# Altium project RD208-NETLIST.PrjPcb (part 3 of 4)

## Sheet 6.SchDoc
size 609 x 444 mm
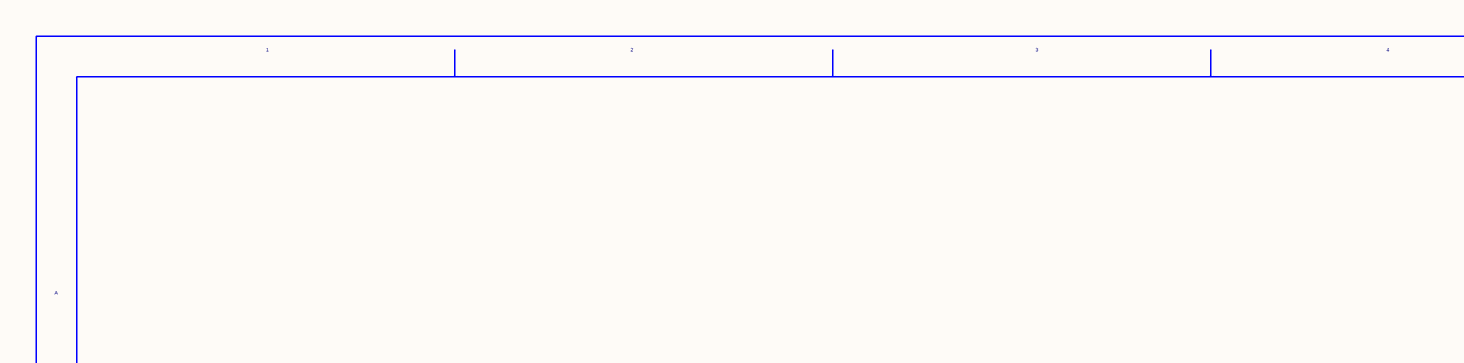
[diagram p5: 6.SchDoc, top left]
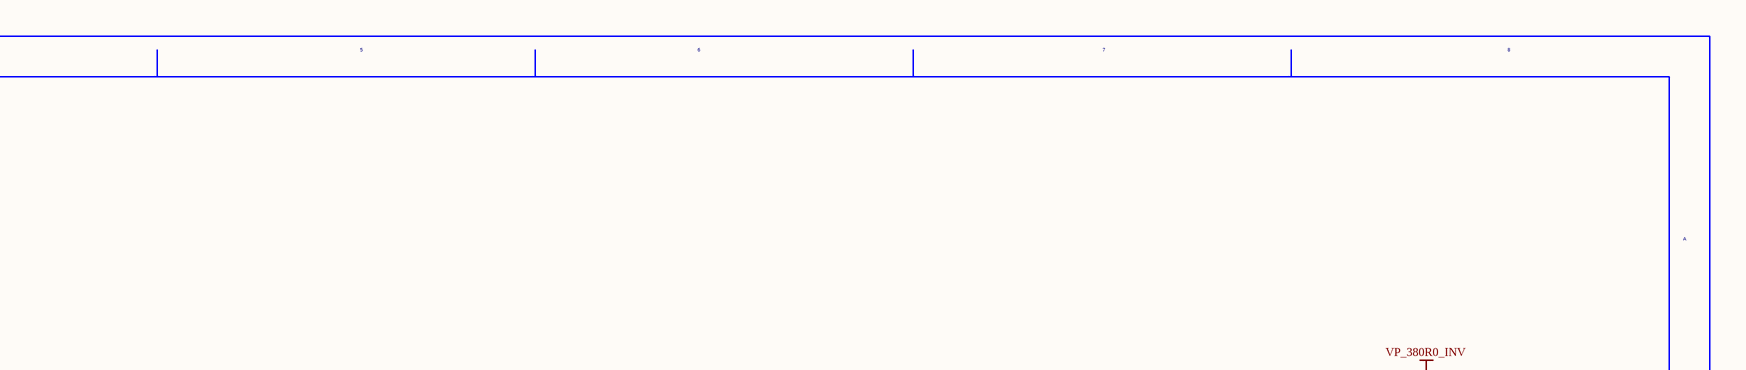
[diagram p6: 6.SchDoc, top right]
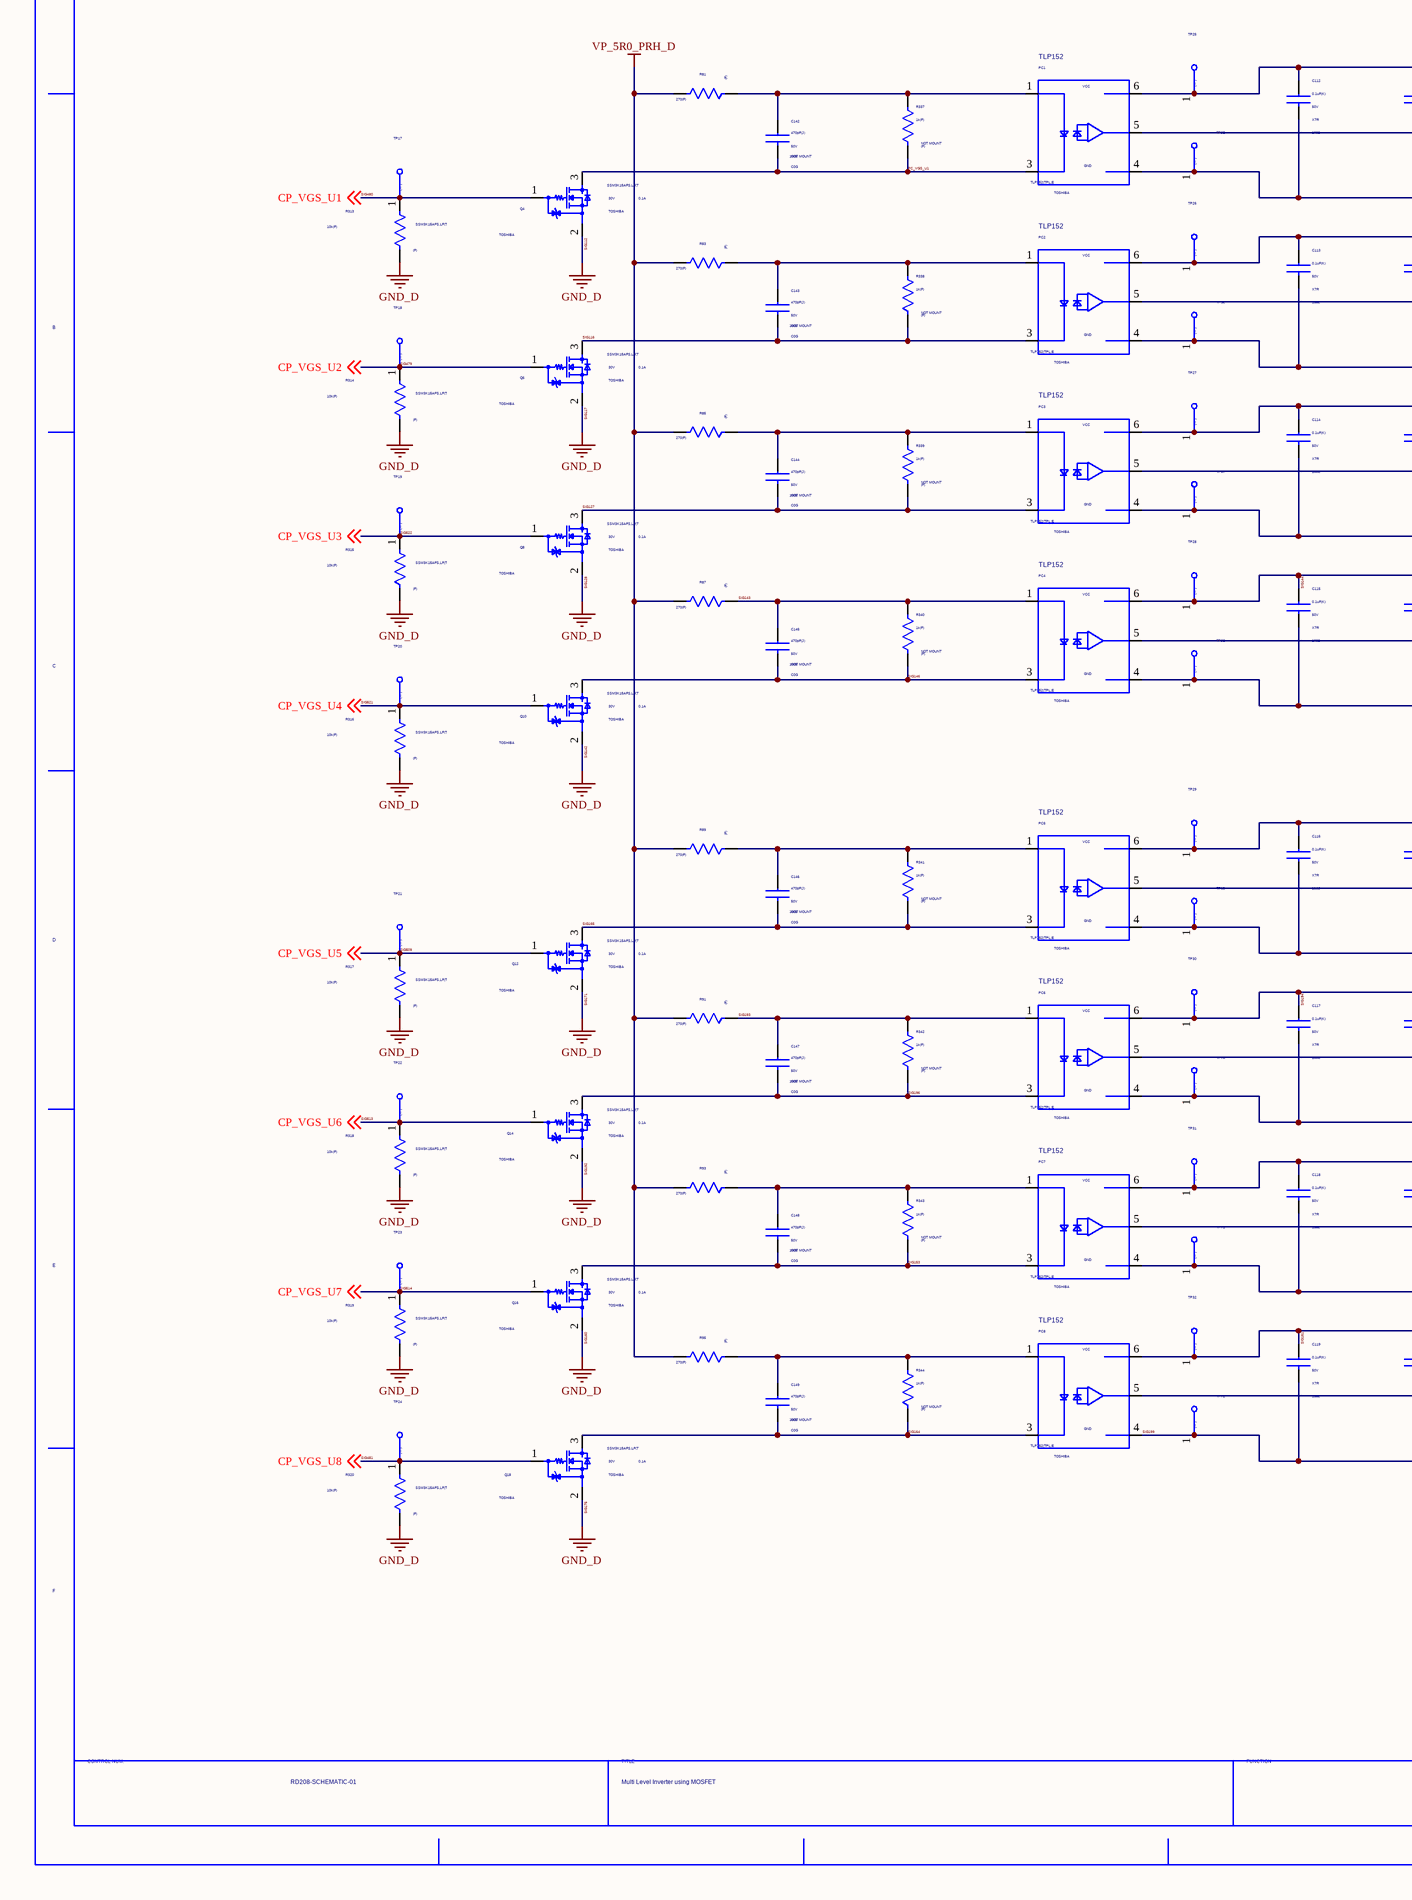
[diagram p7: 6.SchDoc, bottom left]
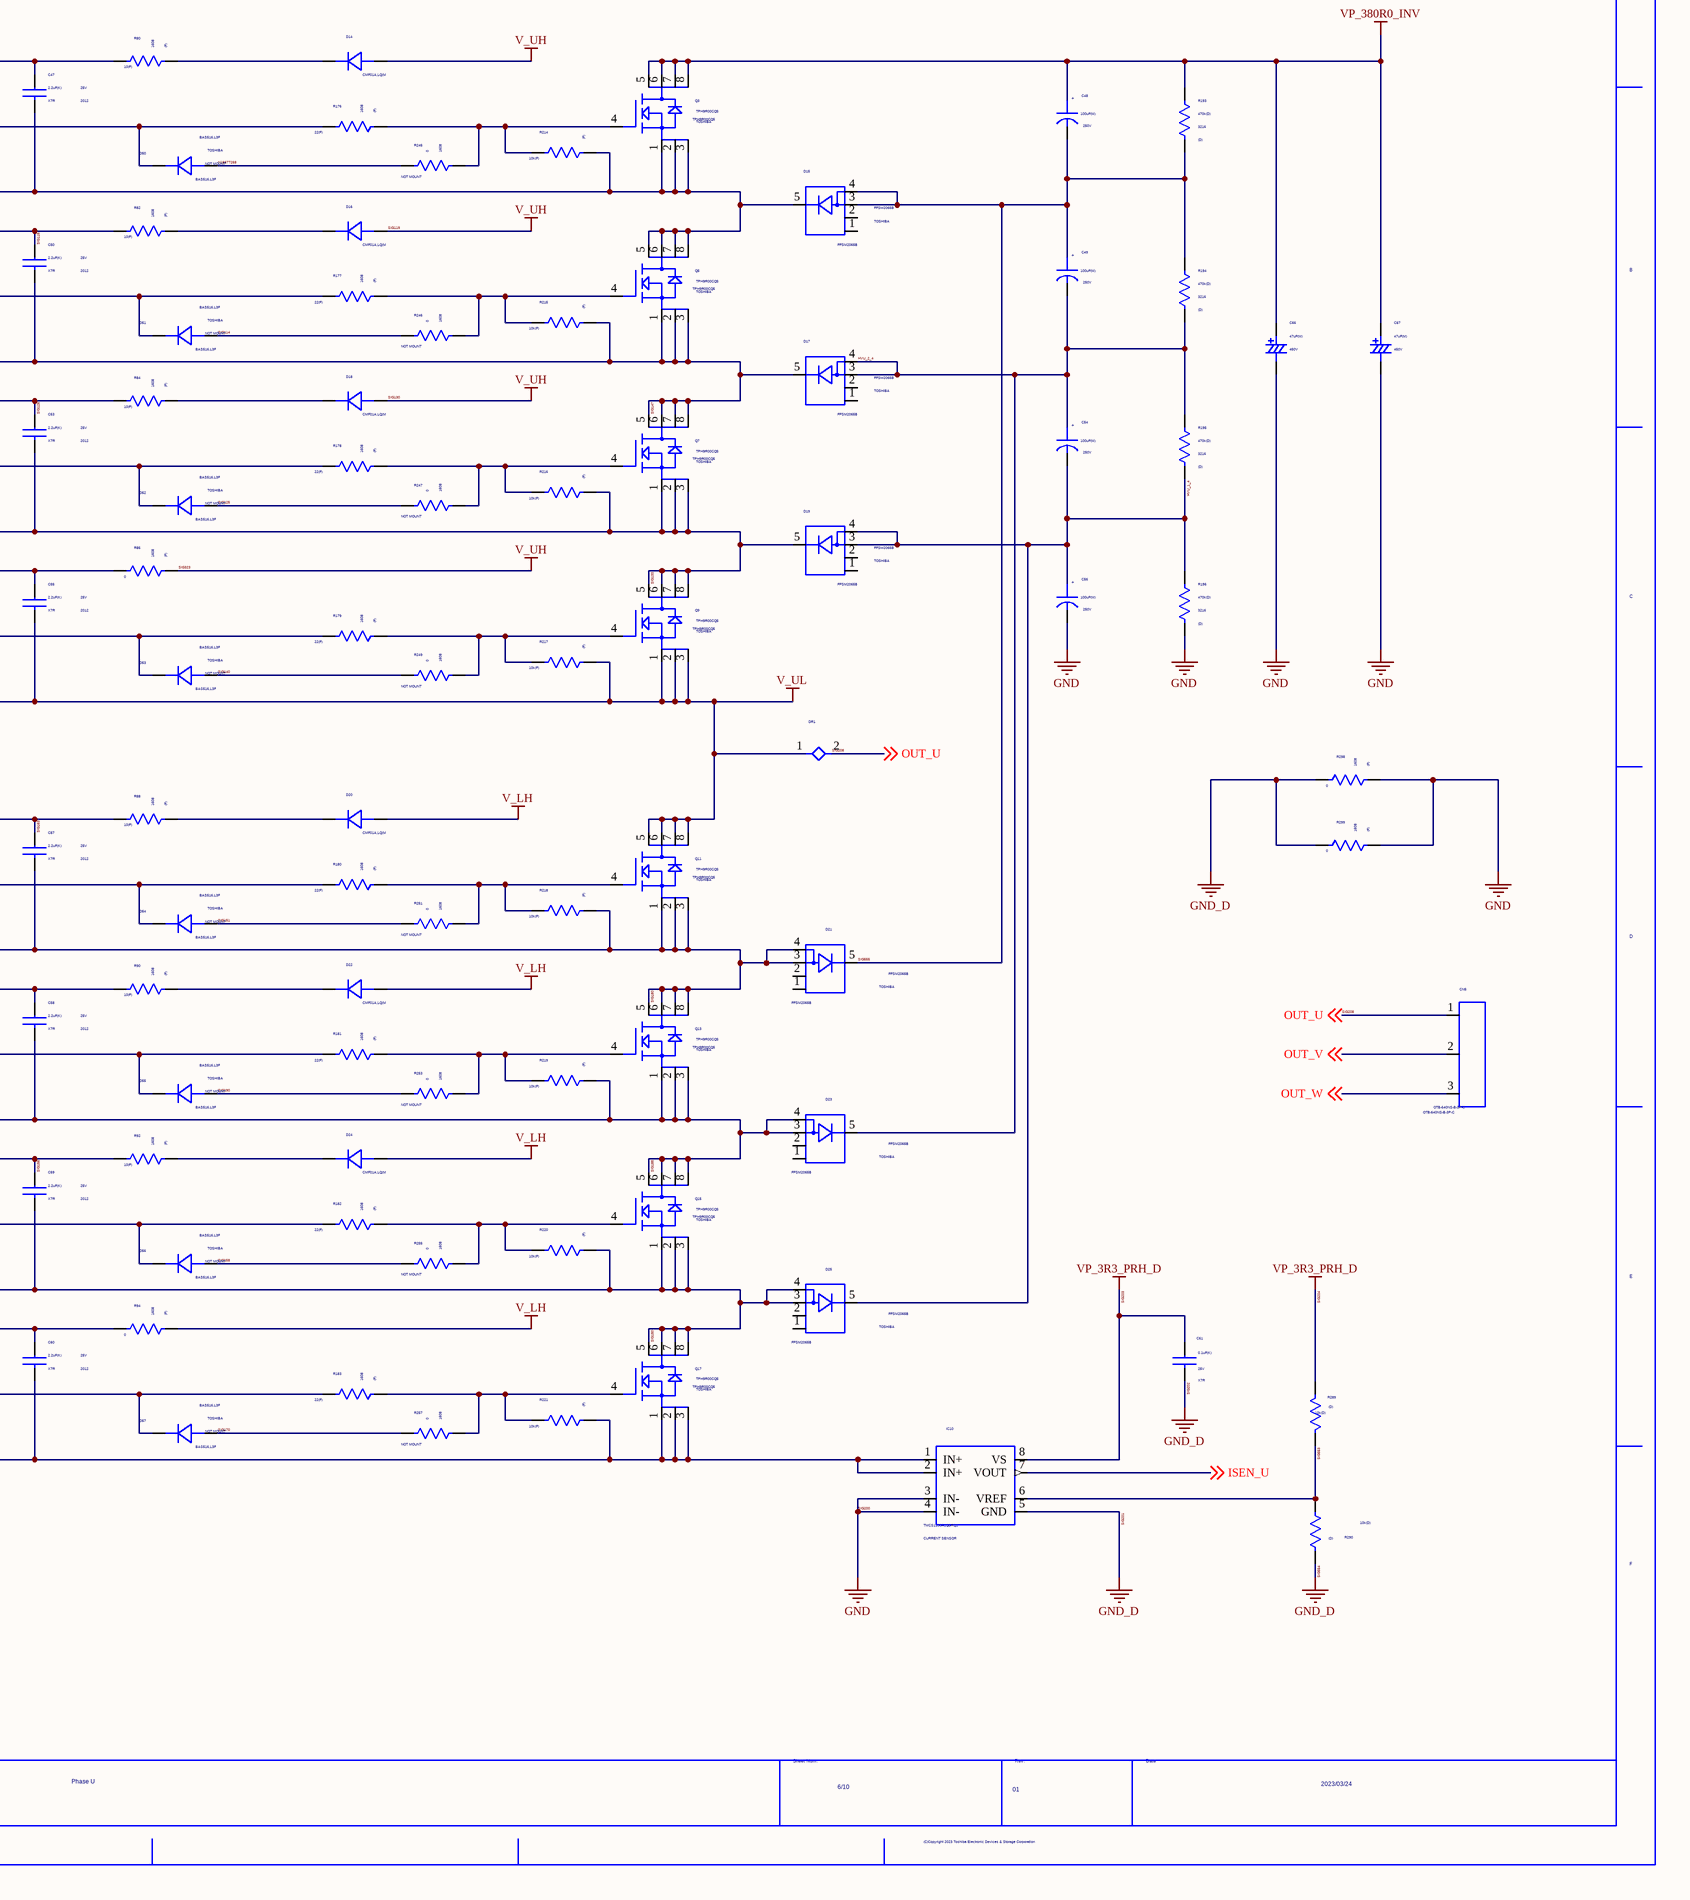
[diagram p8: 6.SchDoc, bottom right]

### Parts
(Parts that share a designator on the sheet are numbered #1, #2 ... from top to bottom, then left to right.)
C47  VAL2: 25V  SIZECODESMD: 2012  VALUE4: X7R  VAL1: 2.2uF(K)  (hidden comment: GRM21BR71E225KE11L)
C48  VAL2: 250V  VAL1: 100uF(M)  (hidden comment: EKMQ251ELL101ML25S)
C49  VAL2: 250V  VAL1: 100uF(M)  (hidden comment: EKMQ251ELL101ML25S)
C50  VAL2: 25V  SIZECODESMD: 2012  VALUE4: X7R  VAL1: 2.2uF(K)  (hidden comment: GRM21BR71E225KE11L)
C53  VAL2: 25V  SIZECODESMD: 2012  VALUE4: X7R  VAL1: 2.2uF(K)  (hidden comment: GRM21BR71E225KE11L)
C54  VAL2: 250V  VAL1: 100uF(M)  (hidden comment: EKMQ251ELL101ML25S)
C55  VAL2: 25V  SIZECODESMD: 2012  VALUE4: X7R  VAL1: 2.2uF(K)  (hidden comment: GRM21BR71E225KE11L)
C56  VAL2: 250V  VAL1: 100uF(M)  (hidden comment: EKMQ251ELL101ML25S)
C57  VAL2: 25V  SIZECODESMD: 2012  VALUE4: X7R  VAL1: 2.2uF(K)  (hidden comment: GRM21BR71E225KE11L)
C58  VAL2: 25V  SIZECODESMD: 2012  VALUE4: X7R  VAL1: 2.2uF(K)  (hidden comment: GRM21BR71E225KE11L)
C59  VAL2: 25V  SIZECODESMD: 2012  VALUE4: X7R  VAL1: 2.2uF(K)  (hidden comment: GRM21BR71E225KE11L)
C60  VAL2: 25V  SIZECODESMD: 2012  VALUE4: X7R  VAL1: 2.2uF(K)  (hidden comment: GRM21BR71E225KE11L)
C61  VAL2: 25V  VALUE4: X7R  VAL1: 0.1uF(K)  (hidden comment: GRM155R71E104KE14D)
C66  VAL2: 450V  VAL1: 47uF(M)  (hidden comment: EKXF451ELL470MM25S)
C67  VAL2: 450V  VAL1: 47uF(M)  (hidden comment: EKXF451ELL470MM25S)
C112  VAL2: 50V  SIZECODESMD: 1608  VALUE4: X7R  VAL1: 0.1uF(K)  (hidden comment: C1608X7R1H104K080AA)
C113  VAL2: 50V  SIZECODESMD: 1608  VALUE4: X7R  VAL1: 0.1uF(K)  (hidden comment: C1608X7R1H104K080AA)
C114  VAL2: 50V  SIZECODESMD: 1608  VALUE4: X7R  VAL1: 0.1uF(K)  (hidden comment: C1608X7R1H104K080AA)
C115  VAL2: 50V  SIZECODESMD: 1608  VALUE4: X7R  VAL1: 0.1uF(K)  (hidden comment: C1608X7R1H104K080AA)
C116  VAL2: 50V  SIZECODESMD: 1608  VALUE4: X7R  VAL1: 0.1uF(K)  (hidden comment: C1608X7R1H104K080AA)
C117  VAL2: 50V  SIZECODESMD: 1608  VALUE4: X7R  VAL1: 0.1uF(K)  (hidden comment: C1608X7R1H104K080AA)
C118  VAL2: 50V  SIZECODESMD: 1608  VALUE4: X7R  VAL1: 0.1uF(K)  (hidden comment: C1608X7R1H104K080AA)
C119  VAL2: 50V  SIZECODESMD: 1608  VALUE4: X7R  VAL1: 0.1uF(K)  (hidden comment: C1608X7R1H104K080AA)
C142  VAL2: 50V  SIZECODESMD: 1005  VALUE4: C0G  VAL1: 470pF(J)  NOTMOUNT: NOT MOUNT  (hidden comment: GRM1555C1H471JA01J)
C143  VAL2: 50V  SIZECODESMD: 1005  VALUE4: C0G  VAL1: 470pF(J)  NOTMOUNT: NOT MOUNT  (hidden comment: GRM1555C1H471JA01J)
C144  VAL2: 50V  SIZECODESMD: 1005  VALUE4: C0G  VAL1: 470pF(J)  NOTMOUNT: NOT MOUNT  (hidden comment: GRM1555C1H471JA01J)
C145  VAL2: 50V  SIZECODESMD: 1005  VALUE4: C0G  VAL1: 470pF(J)  NOTMOUNT: NOT MOUNT  (hidden comment: GRM1555C1H471JA01J)
C146  VAL2: 50V  SIZECODESMD: 1005  VALUE4: C0G  VAL1: 470pF(J)  NOTMOUNT: NOT MOUNT  (hidden comment: GRM1555C1H471JA01J)
C147  VAL2: 50V  SIZECODESMD: 1005  VALUE4: C0G  VAL1: 470pF(J)  NOTMOUNT: NOT MOUNT  (hidden comment: GRM1555C1H471JA01J)
C148  VAL2: 50V  SIZECODESMD: 1005  VALUE4: C0G  VAL1: 470pF(J)  NOTMOUNT: NOT MOUNT  (hidden comment: GRM1555C1H471JA01J)
C149  VAL2: 50V  SIZECODESMD: 1005  VALUE4: C0G  VAL1: 470pF(J)  NOTMOUNT: NOT MOUNT  (hidden comment: GRM1555C1H471JA01J)
CN5  VAL1: OTB-640NS-B-3P-C  (hidden comment: OTB_640NS_B_3P_C)
D14  VAL1: CMF01A,LQ(M  (hidden comment: CMF01A,LQ_M)
D15  USERCOMPTEXT3: TOSHIBA  (hidden comment: FFSM2065B)
D16  VAL1: CMF01A,LQ(M  (hidden comment: CMF01A,LQ_M)
D17  USERCOMPTEXT3: TOSHIBA  (hidden comment: FFSM2065B)
D18  VAL1: CMF01A,LQ(M  (hidden comment: CMF01A,LQ_M)
D19  USERCOMPTEXT3: TOSHIBA  (hidden comment: FFSM2065B)
D20  VAL1: CMF01A,LQ(M  (hidden comment: CMF01A,LQ_M)
D21  USERCOMPTEXT3: TOSHIBA  (hidden comment: FFSM2065B)
D22  VAL1: CMF01A,LQ(M  (hidden comment: CMF01A,LQ_M)
D23  USERCOMPTEXT3: TOSHIBA  (hidden comment: FFSM2065B)
D24  VAL1: CMF01A,LQ(M  (hidden comment: CMF01A,LQ_M)
D25  USERCOMPTEXT3: TOSHIBA  (hidden comment: FFSM2065B)
D50  USERCOMPTEXT3: TOSHIBA  NOTMOUNT: NOT MOUNT  (hidden comment: BAS516,L3F)
D51  USERCOMPTEXT3: TOSHIBA  NOTMOUNT: NOT MOUNT  (hidden comment: BAS516,L3F)
D52  USERCOMPTEXT3: TOSHIBA  NOTMOUNT: NOT MOUNT  (hidden comment: BAS516,L3F)
D53  USERCOMPTEXT3: TOSHIBA  NOTMOUNT: NOT MOUNT  (hidden comment: BAS516,L3F)
D54  USERCOMPTEXT3: TOSHIBA  NOTMOUNT: NOT MOUNT  (hidden comment: BAS516,L3F)
D55  USERCOMPTEXT3: TOSHIBA  NOTMOUNT: NOT MOUNT  (hidden comment: BAS516,L3F)
D56  USERCOMPTEXT3: TOSHIBA  NOTMOUNT: NOT MOUNT  (hidden comment: BAS516,L3F)
D57  USERCOMPTEXT3: TOSHIBA  NOTMOUNT: NOT MOUNT  (hidden comment: BAS516,L3F)
DR1  STAR2  (value not drawn)
IC10  VAL2: CURRENT SENSOR  (hidden comment: TMCS1100A1QDRQ1)
PC1  SCH_NAME: TLP152  USERCOMPTEXT3: TOSHIBA  VAL3: TLP152(TPL,E  (hidden comment: TLP152_TPL,E)
PC2  SCH_NAME: TLP152  USERCOMPTEXT3: TOSHIBA  VAL3: TLP152(TPL,E  (hidden comment: TLP152_TPL,E)
PC3  SCH_NAME: TLP152  USERCOMPTEXT3: TOSHIBA  VAL3: TLP152(TPL,E  (hidden comment: TLP152_TPL,E)
PC4  SCH_NAME: TLP152  USERCOMPTEXT3: TOSHIBA  VAL3: TLP152(TPL,E  (hidden comment: TLP152_TPL,E)
PC5  SCH_NAME: TLP152  USERCOMPTEXT3: TOSHIBA  VAL3: TLP152(TPL,E  (hidden comment: TLP152_TPL,E)
PC6  SCH_NAME: TLP152  USERCOMPTEXT3: TOSHIBA  VAL3: TLP152(TPL,E  (hidden comment: TLP152_TPL,E)
PC7  SCH_NAME: TLP152  USERCOMPTEXT3: TOSHIBA  VAL3: TLP152(TPL,E  (hidden comment: TLP152_TPL,E)
PC8  SCH_NAME: TLP152  USERCOMPTEXT3: TOSHIBA  VAL3: TLP152(TPL,E  (hidden comment: TLP152_TPL,E)
Q3  USERCOMPTEXT3: TOSHIBA  (hidden comment: TPH9R00CQ5)
Q4  VAL2: 0.1A  MANUFACTURER: TOSHIBA  SIZECODESMD: 30V  VAL1: SSM3K15AFS,LF(T  (hidden comment: SSM3K15AFS,LF_T)
Q5  USERCOMPTEXT3: TOSHIBA  (hidden comment: TPH9R00CQ5)
Q6  VAL2: 0.1A  MANUFACTURER: TOSHIBA  SIZECODESMD: 30V  VAL1: SSM3K15AFS,LF(T  (hidden comment: SSM3K15AFS,LF_T)
Q7  USERCOMPTEXT3: TOSHIBA  (hidden comment: TPH9R00CQ5)
Q8  VAL2: 0.1A  MANUFACTURER: TOSHIBA  SIZECODESMD: 30V  VAL1: SSM3K15AFS,LF(T  (hidden comment: SSM3K15AFS,LF_T)
Q9  USERCOMPTEXT3: TOSHIBA  (hidden comment: TPH9R00CQ5)
Q10  VAL2: 0.1A  MANUFACTURER: TOSHIBA  SIZECODESMD: 30V  VAL1: SSM3K15AFS,LF(T  (hidden comment: SSM3K15AFS,LF_T)
Q11  USERCOMPTEXT3: TOSHIBA  (hidden comment: TPH9R00CQ5)
Q12  VAL2: 0.1A  MANUFACTURER: TOSHIBA  SIZECODESMD: 30V  VAL1: SSM3K15AFS,LF(T  (hidden comment: SSM3K15AFS,LF_T)
Q13  USERCOMPTEXT3: TOSHIBA  (hidden comment: TPH9R00CQ5)
Q14  VAL2: 0.1A  MANUFACTURER: TOSHIBA  SIZECODESMD: 30V  VAL1: SSM3K15AFS,LF(T  (hidden comment: SSM3K15AFS,LF_T)
Q15  USERCOMPTEXT3: TOSHIBA  (hidden comment: TPH9R00CQ5)
Q16  VAL2: 0.1A  MANUFACTURER: TOSHIBA  SIZECODESMD: 30V  VAL1: SSM3K15AFS,LF(T  (hidden comment: SSM3K15AFS,LF_T)
Q17  USERCOMPTEXT3: TOSHIBA  (hidden comment: TPH9R00CQ5)
Q18  VAL2: 0.1A  MANUFACTURER: TOSHIBA  SIZECODESMD: 30V  VAL1: SSM3K15AFS,LF(T  (hidden comment: SSM3K15AFS,LF_T)
R80  SIZECODESMD: 1608  VALUE4: (F)  VAL1: 10(F)  (hidden comment: ERJ3EKF10R0V)
R81  VALUE4: (F)  VAL1: 270(F)  (hidden comment: ERJ2RKF2700X)
R82  SIZECODESMD: 1608  VALUE4: (F)  VAL1: 10(F)  (hidden comment: ERJ3EKF10R0V)
R83  VALUE4: (F)  VAL1: 270(F)  (hidden comment: ERJ2RKF2700X)
R84  SIZECODESMD: 1608  VALUE4: (F)  VAL1: 10(F)  (hidden comment: ERJ3EKF10R0V)
R85  VALUE4: (F)  VAL1: 270(F)  (hidden comment: ERJ2RKF2700X)
R86  SIZECODESMD: 1608  VALUE4: (F)  VAL1: 0  (hidden comment: ERJ3EKF10R0V)
R87  VALUE4: (F)  VAL1: 270(F)  (hidden comment: ERJ2RKF2700X)
R88  SIZECODESMD: 1608  VALUE4: (F)  VAL1: 10(F)  (hidden comment: ERJ3EKF10R0V)
R89  VALUE4: (F)  VAL1: 270(F)  (hidden comment: ERJ2RKF2700X)
R90  SIZECODESMD: 1608  VALUE4: (F)  VAL1: 10(F)  (hidden comment: ERJ3EKF10R0V)
R91  VALUE4: (F)  VAL1: 270(F)  (hidden comment: ERJ2RKF2700X)
R92  SIZECODESMD: 1608  VALUE4: (F)  VAL1: 10(F)  (hidden comment: ERJ3EKF10R0V)
R93  VALUE4: (F)  VAL1: 270(F)  (hidden comment: ERJ2RKF2700X)
R94  SIZECODESMD: 1608  VALUE4: (F)  VAL1: 0  (hidden comment: ERJ3EKF10R0V)
R95  VALUE4: (F)  VAL1: 270(F)  (hidden comment: ERJ2RKF2700X)
R176  SIZECODESMD: 1608  VALUE4: (F)  VAL1: 22(F)  (hidden comment: ERJ3EKF22R0V)
R177  SIZECODESMD: 1608  VALUE4: (F)  VAL1: 22(F)  (hidden comment: ERJ3EKF22R0V)
R178  SIZECODESMD: 1608  VALUE4: (F)  VAL1: 22(F)  (hidden comment: ERJ3EKF22R0V)
R179  SIZECODESMD: 1608  VALUE4: (F)  VAL1: 22(F)  (hidden comment: ERJ3EKF22R0V)
R180  SIZECODESMD: 1608  VALUE4: (F)  VAL1: 22(F)  (hidden comment: ERJ3EKF22R0V)
R181  SIZECODESMD: 1608  VALUE4: (F)  VAL1: 22(F)  (hidden comment: ERJ3EKF22R0V)
R182  SIZECODESMD: 1608  VALUE4: (F)  VAL1: 22(F)  (hidden comment: ERJ3EKF22R0V)
R183  SIZECODESMD: 1608  VALUE4: (F)  VAL1: 22(F)  (hidden comment: ERJ3EKF22R0V)
R193  SIZECODESMD: 3216  VALUE4: (D)  VAL1: 470k(D)  (hidden comment: HV73V2BTTD4703D)
R194  SIZECODESMD: 3216  VALUE4: (D)  VAL1: 470k(D)  (hidden comment: HV73V2BTTD4703D)
R195  SIZECODESMD: 3216  VALUE4: (D)  VAL1: 470k(D)  (hidden comment: HV73V2BTTD4703D)
R196  SIZECODESMD: 3216  VALUE4: (D)  VAL1: 470k(D)  (hidden comment: HV73V2BTTD4703D)
R214  VALUE4: (F)  VAL1: 10k(F)  (hidden comment: ERJ2RKF1002X)
R215  VALUE4: (F)  VAL1: 10k(F)  (hidden comment: ERJ2RKF1002X)
R216  VALUE4: (F)  VAL1: 10k(F)  (hidden comment: ERJ2RKF1002X)
R217  VALUE4: (F)  VAL1: 10k(F)  (hidden comment: ERJ2RKF1002X)
R218  VALUE4: (F)  VAL1: 10k(F)  (hidden comment: ERJ2RKF1002X)
R219  VALUE4: (F)  VAL1: 10k(F)  (hidden comment: ERJ2RKF1002X)
R220  VALUE4: (F)  VAL1: 10k(F)  (hidden comment: ERJ2RKF1002X)
R221  VALUE4: (F)  VAL1: 10k(F)  (hidden comment: ERJ2RKF1002X)
R245  SIZECODESMD: 1608  VAL1: 0  NOTMOUNT: NOT MOUNT  (hidden comment: ERJ3GEY0R00V)
R246  SIZECODESMD: 1608  VAL1: 0  NOTMOUNT: NOT MOUNT  (hidden comment: ERJ3GEY0R00V)
R247  SIZECODESMD: 1608  VAL1: 0  NOTMOUNT: NOT MOUNT  (hidden comment: ERJ3GEY0R00V)
R249  SIZECODESMD: 1608  VAL1: 0  NOTMOUNT: NOT MOUNT  (hidden comment: ERJ3GEY0R00V)
R251  SIZECODESMD: 1608  VAL1: 0  NOTMOUNT: NOT MOUNT  (hidden comment: ERJ3GEY0R00V)
R253  SIZECODESMD: 1608  VAL1: 0  NOTMOUNT: NOT MOUNT  (hidden comment: ERJ3GEY0R00V)
R255  SIZECODESMD: 1608  VAL1: 0  NOTMOUNT: NOT MOUNT  (hidden comment: ERJ3GEY0R00V)
R257  SIZECODESMD: 1608  VAL1: 0  NOTMOUNT: NOT MOUNT  (hidden comment: ERJ3GEY0R00V)
R289  VALUE4: (D)  VAL1: 10k(D)  (hidden comment: RK73G1ETTP1002D)
R290  VALUE4: (D)  VAL1: 10k(D)  (hidden comment: RK73G1ETTP1002D)
R298  SIZECODESMD: 1608  VALUE4: (F)  VAL1: 0  (hidden comment: ERJ3EKF10R0V)
R299  SIZECODESMD: 1608  VALUE4: (F)  VAL1: 0  (hidden comment: ERJ3EKF10R0V)
R313  VALUE4: (F)  VAL1: 10k(F)  (hidden comment: ERJ2RKF1002X)
R314  VALUE4: (F)  VAL1: 10k(F)  (hidden comment: ERJ2RKF1002X)
R315  VALUE4: (F)  VAL1: 10k(F)  (hidden comment: ERJ2RKF1002X)
R316  VALUE4: (F)  VAL1: 10k(F)  (hidden comment: ERJ2RKF1002X)
R317  VALUE4: (F)  VAL1: 10k(F)  (hidden comment: ERJ2RKF1002X)
R318  VALUE4: (F)  VAL1: 10k(F)  (hidden comment: ERJ2RKF1002X)
R319  VALUE4: (F)  VAL1: 10k(F)  (hidden comment: ERJ2RKF1002X)
R320  VALUE4: (F)  VAL1: 10k(F)  (hidden comment: ERJ2RKF1002X)
R337  VALUE4: (F)  VAL1: 1k(F)  NOTMOUNT: NOT MOUNT  (hidden comment: ERJ2RKF1001X)
R338  VALUE4: (F)  VAL1: 1k(F)  NOTMOUNT: NOT MOUNT  (hidden comment: ERJ2RKF1001X)
R339  VALUE4: (F)  VAL1: 1k(F)  NOTMOUNT: NOT MOUNT  (hidden comment: ERJ2RKF1001X)
R340  VALUE4: (F)  VAL1: 1k(F)  NOTMOUNT: NOT MOUNT  (hidden comment: ERJ2RKF1001X)
R341  VALUE4: (F)  VAL1: 1k(F)  NOTMOUNT: NOT MOUNT  (hidden comment: ERJ2RKF1001X)
R342  VALUE4: (F)  VAL1: 1k(F)  NOTMOUNT: NOT MOUNT  (hidden comment: ERJ2RKF1001X)
R343  VALUE4: (F)  VAL1: 1k(F)  NOTMOUNT: NOT MOUNT  (hidden comment: ERJ2RKF1001X)
R344  VALUE4: (F)  VAL1: 1k(F)  NOTMOUNT: NOT MOUNT  (hidden comment: ERJ2RKF1001X)
TP17  TP  (value not drawn)
TP18  TP  (value not drawn)
TP19  TP  (value not drawn)
TP20  TP  (value not drawn)
TP21  TP  (value not drawn)
TP22  TP  (value not drawn)
TP23  TP  (value not drawn)
TP24  TP  (value not drawn)
TP25  TP  (value not drawn)
TP26  TP  (value not drawn)
TP27  TP  (value not drawn)
TP28  TP  (value not drawn)
TP29  TP  (value not drawn)
TP30  TP  (value not drawn)
TP31  TP  (value not drawn)
TP32  TP  (value not drawn)
TP65  TP  (value not drawn)
TP66  TP  (value not drawn)
TP67  TP  (value not drawn)
TP68  TP  (value not drawn)
TP69  TP  (value not drawn)
TP70  TP  (value not drawn)
TP71  TP  (value not drawn)
TP72  TP  (value not drawn)
U?#6  DATE: 2023/03/24  TITLE: Multi Level Inverter using MOSFET  REVISION: 01  SHEETNUMBER: 6/10  DRAWINGNUMBER: RD208-SCHEMATIC-01  FUNCTION: Phase U  (hidden comment: WAKU_DEF_A3)

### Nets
GND_D: C61.2 IC10.5(GND) Q4.2(E) Q6.2(E) Q8.2(E) Q10.2(E) Q12.2(E) Q14.2(E) Q16.2(E) Q18.2(E) R290.2 R298.1 R299.1 R313.2 R314.2 R315.2 R316.2 R317.2 R318.2 R319.2 R320.2  [also labelled SIG112, SIG117, SIG128, SIG142, SIG160, SIG171, SIG175, SIG192, SIG201, SIG202, SIG554]  [project net SIG10]
SIG119: D14.A(ANODE) D16.A(ANODE) D18.A(ANODE) R86.2  [also labelled SIG130, SIG323, V_UH]
SIG200: C56.2 C66.2 C67.2 IC10.3(IN-) IC10.4(IN-) R196.2 R298.2 R299.2  [also labelled GND]
SIG203: C61.1 IC10.8(VS) R289.2  [also labelled SIG204, VP_3R3_PRH_D]  [project net SIG107]
V_LH: D20.A(ANODE) D22.A(ANODE) D24.A(ANODE) R94.2  [project net SIG235]
V_UL: C55.2 C115.2 DR1.1 PC4.4 Q9.1(S1) Q9.2(S2) Q9.3(S3) Q11.5(D1) Q11.6(D2) Q11.7(D3) Q11.8(D4) R217.2 TP68.1
VP_5R0_PRH_D: R81.1 R83.1 R85.1 R87.1 R89.1 R91.1 R93.1 R95.1  [project net SIG104]
VP_380R0_INV: C48.1 C66.1 C67.1 Q3.5(D1) Q3.6(D2) Q3.7(D3) Q3.8(D4) R193.1  [project net SIG1]
BS_U1: D14.K(CATHODE) R80.2
GD_U1: Q3.4(G) R176.2 R214.1 R245.2
GD_U2: Q5.4(G) R177.2 R215.1 R246.2
GD_U3: Q7.4(G) R178.2 R216.1 R247.2
GD_U5: Q11.4(G) R180.2 R218.1 R251.2
GD_U6: Q13.4(G) R181.2 R219.1 R253.2
GD_U7: Q15.4(G) R182.2 R220.1 R255.2
GD_U8: Q17.4(G) R183.2 R221.1 R257.2
HVU_1_4: C54.2 C56.1 D19.3(ANODE3) D19.4(ANODE4) D25.5(CATHODE) R195.2 R196.1
HVU_2_4: C49.2 C54.1 D17.3(ANODE3) D17.4(ANODE4) D23.5(CATHODE) R194.2 R195.1
ISEN_U: IC10.7(VOUT) ; off-sheet ISEN_U
N16677268: D50.A(ANODE) R245.1
OUT_V: CN5.2 ; off-sheet OUT_V
OUT_W: CN5.3 ; off-sheet OUT_W
PC_ANODE_U1: C142.1 PC1.1 R81.2 R337.1
PC_G_U1: C47.2 C112.2 D15.5(CATHODE) PC1.4 Q3.1(S1) Q3.2(S2) Q3.3(S3) Q5.5(D1) Q5.6(D2) Q5.7(D3) Q5.8(D4) R214.2 TP65.1
PC_GD_U1: D50.K(CATHODE) PC1.5 R176.1
PC_V_U1: C47.1 C112.1 PC1.6 R80.1 TP25.1
PC_VGS_U1: C142.2 PC1.3 Q4.3(C) R337.2
SIG113: C143.1 PC2.1 R83.2 R338.1
SIG114: D51.A(ANODE) R246.1
SIG115: C50.1 C113.1 PC2.6 R82.1 TP26.1
SIG116: C143.2 PC2.3 Q6.3(C) R338.2
SIG122: D51.K(CATHODE) PC2.5 R177.1
SIG123: D16.K(CATHODE) R82.2
SIG124: C144.1 PC3.1 R85.2 R339.1
SIG125: D52.A(ANODE) R247.1
SIG126: C53.1 C114.1 PC3.6 R84.1 TP27.1
SIG127: C144.2 PC3.3 Q8.3(C) R339.2
SIG133: C53.2 C114.2 D19.5(CATHODE) PC3.4 Q7.1(S1) Q7.2(S2) Q7.3(S3) Q9.5(D1) Q9.6(D2) Q9.7(D3) Q9.8(D4) R216.2 TP67.1
SIG134: D52.K(CATHODE) PC3.5 R178.1
SIG136: D53.K(CATHODE) PC4.5 R179.1
SIG137: D18.K(CATHODE) R84.2
SIG140: D53.A(ANODE) R249.1
SIG143: C145.1 PC4.1 R87.2 R340.1
SIG144: C55.1 C115.1 PC4.6 R86.1 TP28.1
SIG145: Q9.4(G) R179.2 R217.1 R249.2
SIG146: C145.2 PC4.3 Q10.3(C) R340.2
SIG147: C50.2 C113.2 D17.5(CATHODE) PC2.4 Q5.1(S1) Q5.2(S2) Q5.3(S3) Q7.5(D1) Q7.6(D2) Q7.7(D3) Q7.8(D4) R215.2 TP66.1
SIG149: C146.1 PC5.1 R89.2 R341.1
SIG150: C59.2 C118.2 D25.3(ANODE3) D25.4(ANODE4) PC7.4 Q15.1(S1) Q15.2(S2) Q15.3(S3) Q17.5(D1) Q17.6(D2) Q17.7(D3) Q17.8(D4) R220.2 TP71.1
SIG151: D54.A(ANODE) R251.1
SIG153: C148.2 PC7.3 Q16.3(C) R343.2
SIG154: C148.1 PC7.1 R93.2 R343.1
SIG156: C59.1 C118.1 PC7.6 R92.1 TP31.1
SIG158: D56.A(ANODE) R255.1
SIG161: C60.1 C119.1 PC8.6 R94.1 TP32.1
SIG163: C57.1 C116.1 PC5.6 R88.1 TP29.1
SIG164: C149.2 PC8.3 Q18.3(C) R344.2
SIG165: C146.2 PC5.3 Q12.3(C) R341.2
SIG166: D57.K(CATHODE) PC8.5 R183.1
SIG170: D57.A(ANODE) R257.1
SIG174: C149.1 PC8.1 R95.2 R344.1
SIG176: D24.K(CATHODE) R92.2
SIG180: C57.2 C116.2 D21.3(ANODE3) D21.4(ANODE4) PC5.4 Q11.1(S1) Q11.2(S2) Q11.3(S3) Q13.5(D1) Q13.6(D2) Q13.7(D3) Q13.8(D4) R218.2 TP69.1
SIG182: D54.K(CATHODE) PC5.5 R180.1
SIG183: D22.K(CATHODE) R90.2
SIG184: D56.K(CATHODE) PC7.5 R182.1
SIG185: C58.2 C117.2 D23.3(ANODE3) D23.4(ANODE4) PC6.4 Q13.1(S1) Q13.2(S2) Q13.3(S3) Q15.5(D1) Q15.6(D2) Q15.7(D3) Q15.8(D4) R219.2 TP70.1
SIG186: D55.K(CATHODE) PC6.5 R181.1
SIG187: D20.K(CATHODE) R88.2
SIG190: D55.A(ANODE) R253.1
SIG193: C147.1 PC6.1 R91.2 R342.1
SIG194: C58.1 C117.1 PC6.6 R90.1 TP30.1
SIG196: C147.2 PC6.3 Q14.3(C) R342.2
SIG199: C60.2 C119.2 IC10.1(IN+) IC10.2(IN+) PC8.4 Q17.1(S1) Q17.2(S2) Q17.3(S3) R221.2 TP72.1
SIG208: CN5.1 DR1.2 ; off-sheet OUT_U  [also labelled OUT_U]
SIG479: Q6.1(B) R314.1 TP18.1 ; off-sheet CP_VGS_U2  [also labelled CP_VGS_U2]
SIG480: Q4.1(B) R313.1 TP17.1 ; off-sheet CP_VGS_U1  [also labelled CP_VGS_U1]
SIG481: Q18.1(B) R320.1 TP24.1 ; off-sheet CP_VGS_U8  [also labelled CP_VGS_U8]
SIG509: Q12.1(B) R317.1 TP21.1 ; off-sheet CP_VGS_U5  [also labelled CP_VGS_U5]
SIG513: Q14.1(B) R318.1 TP22.1 ; off-sheet CP_VGS_U6  [also labelled CP_VGS_U6]
SIG514: Q16.1(B) R319.1 TP23.1 ; off-sheet CP_VGS_U7  [also labelled CP_VGS_U7]
SIG521: Q10.1(B) R316.1 TP20.1 ; off-sheet CP_VGS_U4  [also labelled CP_VGS_U4]
SIG522: Q8.1(B) R315.1 TP19.1 ; off-sheet CP_VGS_U3  [also labelled CP_VGS_U3]
SIG553: IC10.6(VREF) R289.1 R290.1
SIG555: C48.2 C49.1 D15.3(ANODE3) D15.4(ANODE4) D21.5(CATHODE) R193.2 R194.1

Not connected (* = marked no-connect by the designer): D15 1(NC1) 2(NC2); D17 1(NC1) 2(NC2); D19 1(NC1) 2(NC2); D21 1(NC1) 2(NC2); D23 1(NC1) 2(NC2); D25 1(NC1) 2(NC2)

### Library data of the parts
C47 C50 C53 C55 C57-C60 = GRM21BR71E225KE11L: MANUFACTURER: MURATA; ITEM: CAP Ceramic; TIME: 08:44:45; UPDATEUSER: t5459927; SAVECOUNT: 1; OriginalSymbolOrigin: (0,0); INSTANCENAME: INS15860000
C48 = EKMQ251ELL101ML25S: MANUFACTURER: Nippon Chemi-Con; ITEM: CAP ALUM; TIME: 08:44:45; UPDATEUSER: t5459927; SAVECOUNT: 1; OriginalSymbolOrigin: (0,2540); INSTANCENAME: INS16070082
C49 = EKMQ251ELL101ML25S: MANUFACTURER: Nippon Chemi-Con; ITEM: CAP ALUM; TIME: 08:44:45; UPDATEUSER: t5459927; SAVECOUNT: 1; OriginalSymbolOrigin: (0,2540); INSTANCENAME: INS16070102
C54 = EKMQ251ELL101ML25S: MANUFACTURER: Nippon Chemi-Con; ITEM: CAP ALUM; TIME: 08:44:45; UPDATEUSER: t5459927; SAVECOUNT: 1; OriginalSymbolOrigin: (0,2540); INSTANCENAME: INS16070122
C56 = EKMQ251ELL101ML25S: MANUFACTURER: Nippon Chemi-Con; ITEM: CAP ALUM; TIME: 08:44:45; UPDATEUSER: t5459927; SAVECOUNT: 1; OriginalSymbolOrigin: (0,2540); INSTANCENAME: INS16070142
C61 = GRM155R71E104KE14D: MANUFACTURER: MURATA; ITEM: CAP Ceramic; SIZECODESMD: 1005; TIME: 08:44:45; UPDATEUSER: t5459927; SAVECOUNT: 1; OriginalSymbolOrigin: (0,0); INSTANCENAME: INS16776295
C66 = EKXF451ELL470MM25S: MANUFACTURER: Nippon Chemi-Con; ITEM: CAP ALUM; SIZECODESMD: 18.0mm; TIME: 08:44:46; UPDATEUSER: t5459927; SAVECOUNT: 1; OriginalSymbolOrigin: (0,0); INSTANCENAME: INS16806395
C67 = EKXF451ELL470MM25S: MANUFACTURER: Nippon Chemi-Con; ITEM: CAP ALUM; SIZECODESMD: 18.0mm; TIME: 08:44:46; UPDATEUSER: t5459927; SAVECOUNT: 1; OriginalSymbolOrigin: (0,0); INSTANCENAME: INS16806405
C112-C119 = C1608X7R1H104K080AA: MANUFACTURER: TDK; ITEM: CAP Ceramic; TIME: 08:44:45; UPDATEUSER: t5459927; SAVECOUNT: 1; OriginalSymbolOrigin: (0,0); INSTANCENAME: INS16097035
C142-C149 = GRM1555C1H471JA01J: MANUFACTURER: MURATA; ITEM: CAP Ceramic; TIME: 08:44:46; UPDATEUSER: t5459927; SAVECOUNT: 1; OriginalSymbolOrigin: (0,0); INSTANCENAME: INS17224098
CN5 = OTB_640NS_B_3P_C: MANUFACTURER: OSADA; ITEM: Connector; VAL2: 11mm   x3; TIME: 08:44:46; UPDATEUSER: PS4_common_PC; UPDATETIME: 15:40:04; SAVECOUNT: 2; SAVEAREA0: -13992,-20726,15872,1136; OriginalSymbolOrigin: (0,0)
D14 D16 D18 D20 D22 D24 = CMF01A,LQ_M: MANUFACTURER: TOSHIBA; COMP: CMF01A_LQ_M; ITEM: DIODE; TIME: 08:44:46; UPDATEUSER: t5459927; SAVECOUNT: 1; OriginalSymbolOrigin: (0,0); INSTANCENAME: INS15860772
D15 D17 D19 D21 D23 D25 = FFSM2065B: MANUFACTURER: ON_SEMI; ITEM: DIODE; TIME: 08:44:45; UPDATEUSER: t5459927; SAVECOUNT: 1; SAVEAREA0: -3235,-11101,10576,-990; OriginalSymbolOrigin: (0,0); INSTANCENAME: INS16711377
D50-D57 = BAS516,L3F: COMP: BAS516_L3F; ITEM: DIODE; TIME: 08:44:45; UPDATEUSER: t5459927; SAVECOUNT: 1; OriginalSymbolOrigin: (0,0); INSTANCENAME: INS16674713
DR1 = STAR2: TIME: 12:37:47; UPDATEUSER: d5009410; UPDATETIME: 12:51:51; SAVECOUNT: 17; SAVEAREA0: -6564,-5245,9999,5672; OriginalSymbolOrigin: (-2540,2540); COMP: ONEPOINT
IC10 = TMCS1100A1QDRQ1: MANUFACTURER: TI; ITEM: IC CurrentSensor; TIME: 08:44:45; UPDATEUSER: PS4_common_PC; UPDATETIME: 16:01:14; SAVECOUNT: 3; SAVEAREA0: -10605,-15555,25377,840; OriginalSymbolOrigin: (0,0)
PC1-PC8 = TLP152_TPL,E: ITEM: Photocoupler; COMP: TLP152_TPL_E; TIME: 08:44:45; UPDATEUSER: t5459927; SAVECOUNT: 1; OriginalSymbolOrigin: (0,0); INSTANCENAME: INS15861608
Q3 Q5 Q7 Q9 Q11 Q13 Q15 Q17 = TPH9R00CQ5: ITEM: FET; ORDER: 0; TIME: 08:44:45; UPDATEUSER: t5459927; SAVECOUNT: 1; OriginalSymbolOrigin: (0,0); INSTANCENAME: INS15860992
Q4 Q6 Q8 Q10 Q12 Q14 Q16 Q18 = SSM3K15AFS,LF_T: ITEM: Digital Transistor NPN; COMP: SSM3K15AFS-123; ORDER: 0; TIME: 08:44:45; UPDATEUSER: t5459927; SAVECOUNT: 1; OriginalSymbolOrigin: (0,0); INSTANCENAME: INS15859756
R80 R82 R84 R88 R90 R92 = ERJ3EKF10R0V: MANUFACTURER: Panasonic; ITEM: Register; VAL2: 100mW; TIME: 08:44:45; UPDATEUSER: t5459927; SAVECOUNT: 1; OriginalSymbolOrigin: (0,0); INSTANCENAME: INS16646496
R81 R83 R85 R87 R89 R91 R93 R95 = ERJ2RKF2700X: MANUFACTURER: Panasonic; ITEM: Register; VAL2: 100mW; SIZECODESMD: 1005; TIME: 08:44:45; UPDATEUSER: t5459927; SAVECOUNT: 1; OriginalSymbolOrigin: (0,0); INSTANCENAME: INS16151457
R86 R94 R298 R299 = ERJ3EKF10R0V: MANUFACTURER: Panasonic; ITEM: Register; VAL2: 1/10W; COMP: ERJ3GEY0R00V; TIME: 08:44:45; UPDATEUSER: t5459927; SAVECOUNT: 1; OriginalSymbolOrigin: (0,0); INSTANCENAME: INS16646496
R176-R183 = ERJ3EKF22R0V: MANUFACTURER: Panasonic; ITEM: Register; VAL2: 100mW; TIME: 08:44:45; UPDATEUSER: t5459927; SAVECOUNT: 1; OriginalSymbolOrigin: (0,0); INSTANCENAME: INS17210794
R193 = HV73V2BTTD4703D: MANUFACTURER: KOA; ITEM: Register; VAL2: 0.33W; TIME: 08:44:45; UPDATEUSER: t5459927; SAVECOUNT: 1; OriginalSymbolOrigin: (0,0); INSTANCENAME: INS16806843
R194 = HV73V2BTTD4703D: MANUFACTURER: KOA; ITEM: Register; VAL2: 0.33W; TIME: 08:44:45; UPDATEUSER: t5459927; SAVECOUNT: 1; OriginalSymbolOrigin: (0,0); INSTANCENAME: INS16806859
R195 = HV73V2BTTD4703D: MANUFACTURER: KOA; ITEM: Register; VAL2: 0.33W; TIME: 08:44:45; UPDATEUSER: t5459927; SAVECOUNT: 1; OriginalSymbolOrigin: (0,0); INSTANCENAME: INS16806875
R196 = HV73V2BTTD4703D: MANUFACTURER: KOA; ITEM: Register; VAL2: 0.33W; TIME: 08:44:45; UPDATEUSER: t5459927; SAVECOUNT: 1; OriginalSymbolOrigin: (0,0); INSTANCENAME: INS16806891
R214-R221 = ERJ2RKF1002X: MANUFACTURER: Panasonic; ITEM: Register; VAL2: 100mW; SIZECODESMD: 1005; TIME: 08:44:45; UPDATEUSER: t5459927; SAVECOUNT: 1; OriginalSymbolOrigin: (0,0); INSTANCENAME: INS16648754
R245-R247 R249 R251 R253 R255 R257 = ERJ3GEY0R00V: MANUFACTURER: Panasonic; ITEM: Register; VAL2: 1/10W; TIME: 08:44:45; UPDATEUSER: t5459927; SAVECOUNT: 1; OriginalSymbolOrigin: (0,0); INSTANCENAME: INS16674743
R289 = RK73G1ETTP1002D: MANUFACTURER: KOA; ITEM: Register; VAL2: 100mW; SIZECODESMD: 1005; TIME: 08:44:46; UPDATEUSER: t5459927; SAVECOUNT: 1; OriginalSymbolOrigin: (0,0); INSTANCENAME: INS16808670
R290 = RK73G1ETTP1002D: MANUFACTURER: KOA; ITEM: Register; VAL2: 100mW; SIZECODESMD: 1005; TIME: 08:44:46; UPDATEUSER: t5459927; SAVECOUNT: 1; OriginalSymbolOrigin: (0,0); INSTANCENAME: INS16808683
R313-R320 = ERJ2RKF1002X: MANUFACTURER: Panasonic; ITEM: Register; VAL2: 100mW; SIZECODESMD: 1005; TIME: 08:44:45; UPDATEUSER: t5459927; SAVECOUNT: 1; OriginalSymbolOrigin: (0,0); INSTANCENAME: INS17222356
R337-R344 = ERJ2RKF1001X: MANUFACTURER: Panasonic; ITEM: Register; VAL2: 100mW; SIZECODESMD: 1005; TIME: 08:44:45; UPDATEUSER: t5459927; SAVECOUNT: 1; OriginalSymbolOrigin: (0,0); INSTANCENAME: INS17224061
TP17-TP32 TP65-TP72 = TP: TIME: 16:12:21; UPDATEUSER: fukuda-y; UPDATETIME: 16:18:11; SAVECOUNT: 2; SAVEAREA0: -242,-92,12810,7836; OriginalSymbolOrigin: (0,7620); VAL3: TH Hole dia. 1.0; COMP: TP-TH1.0-L1.6
U?#6 = WAKU_DEF_A3: PLOTTIME: HH:MM; SAVEAREA0: -311037,-554865,914355,115662; TIME: 14:30:25; UPDATEUSER: PS4_common_PC; UPDATETIME: 08:25:02; SAVECOUNT: 18; ZONEOFFSETX: 36; ZONEOFFSETY: -24; OriginalSymbolOrigin: (12700,-12700)

## Sheet 7.SchDoc
size 609 x 444 mm
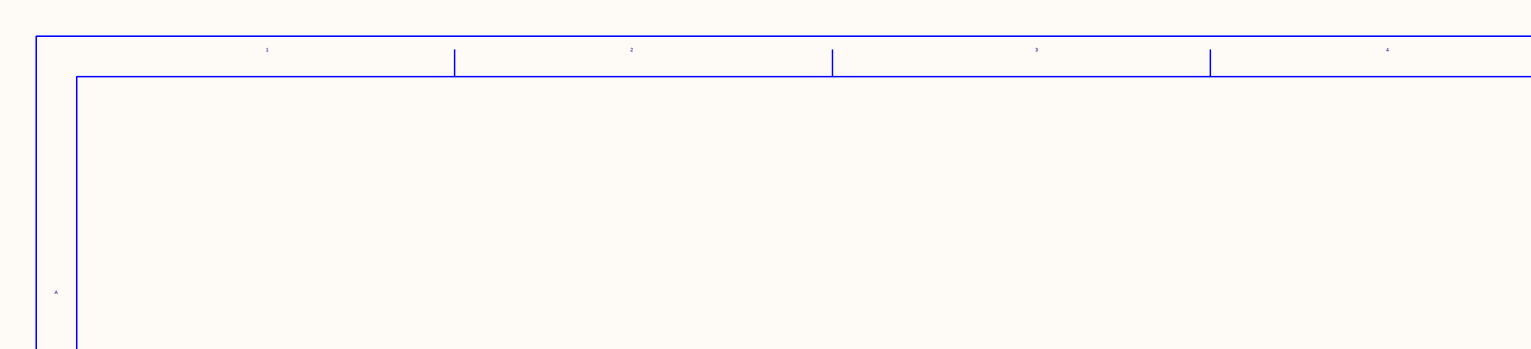
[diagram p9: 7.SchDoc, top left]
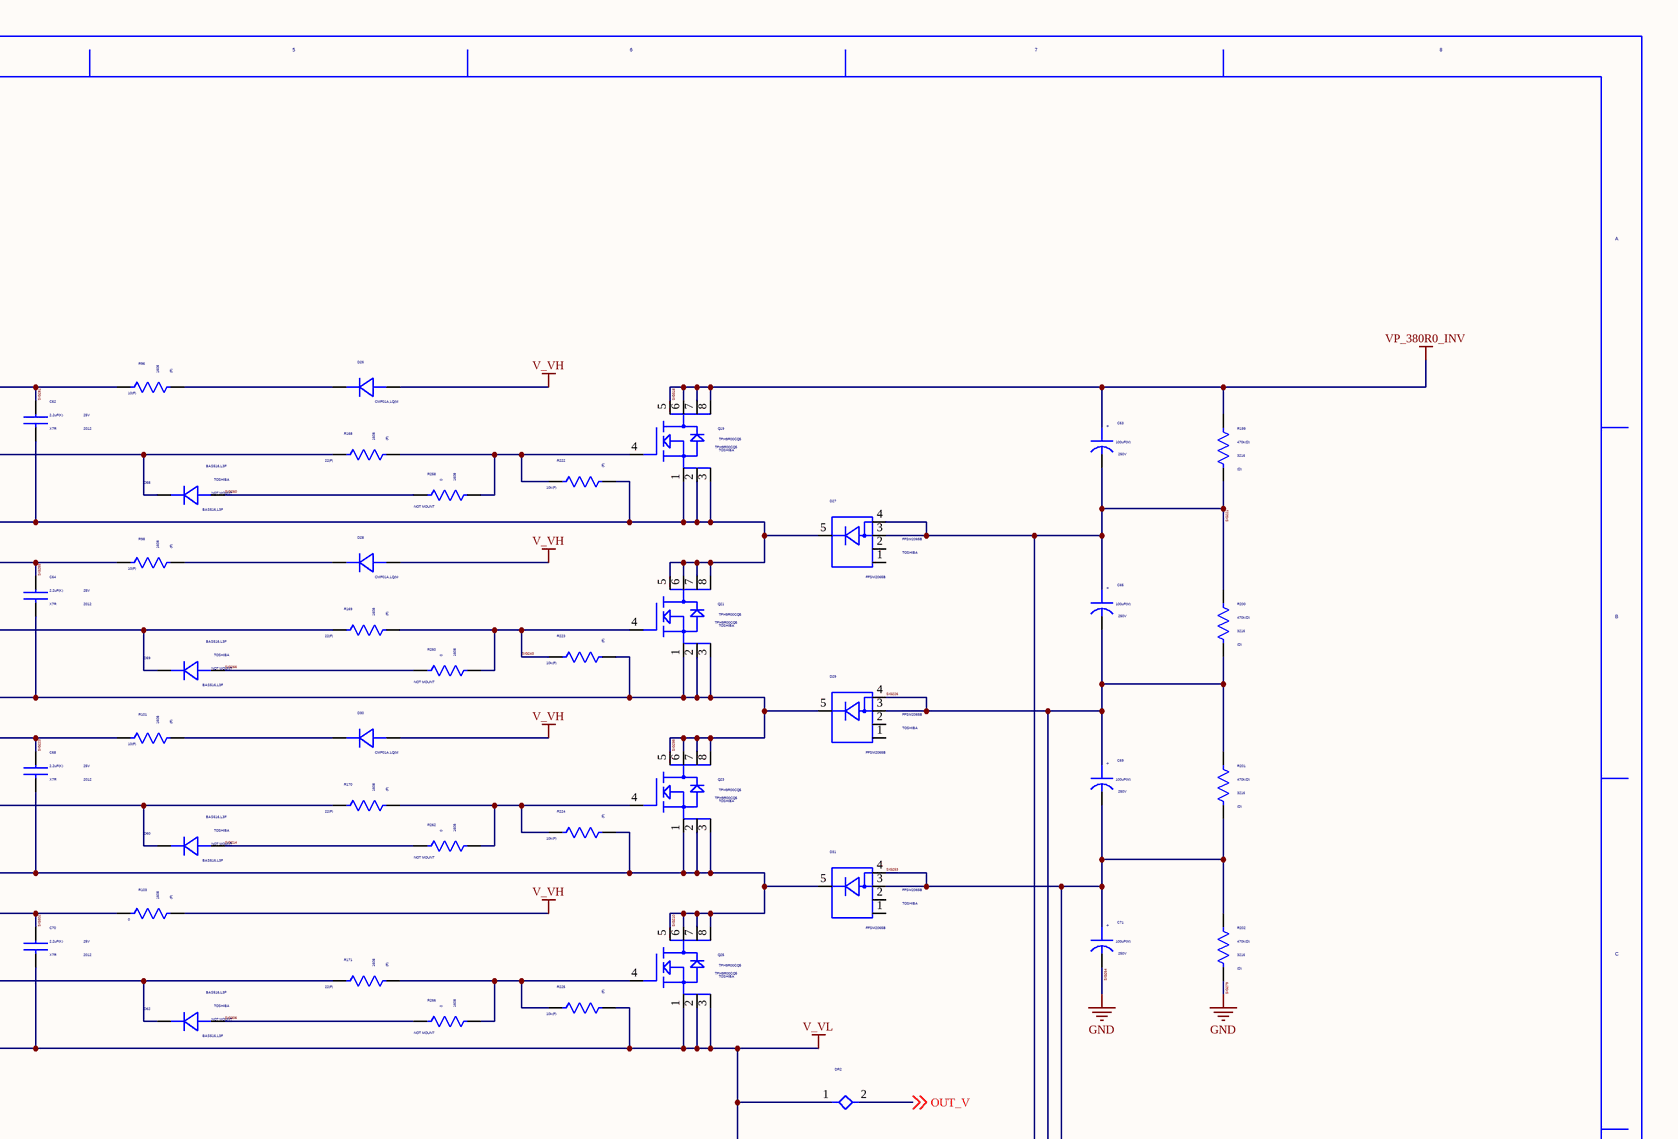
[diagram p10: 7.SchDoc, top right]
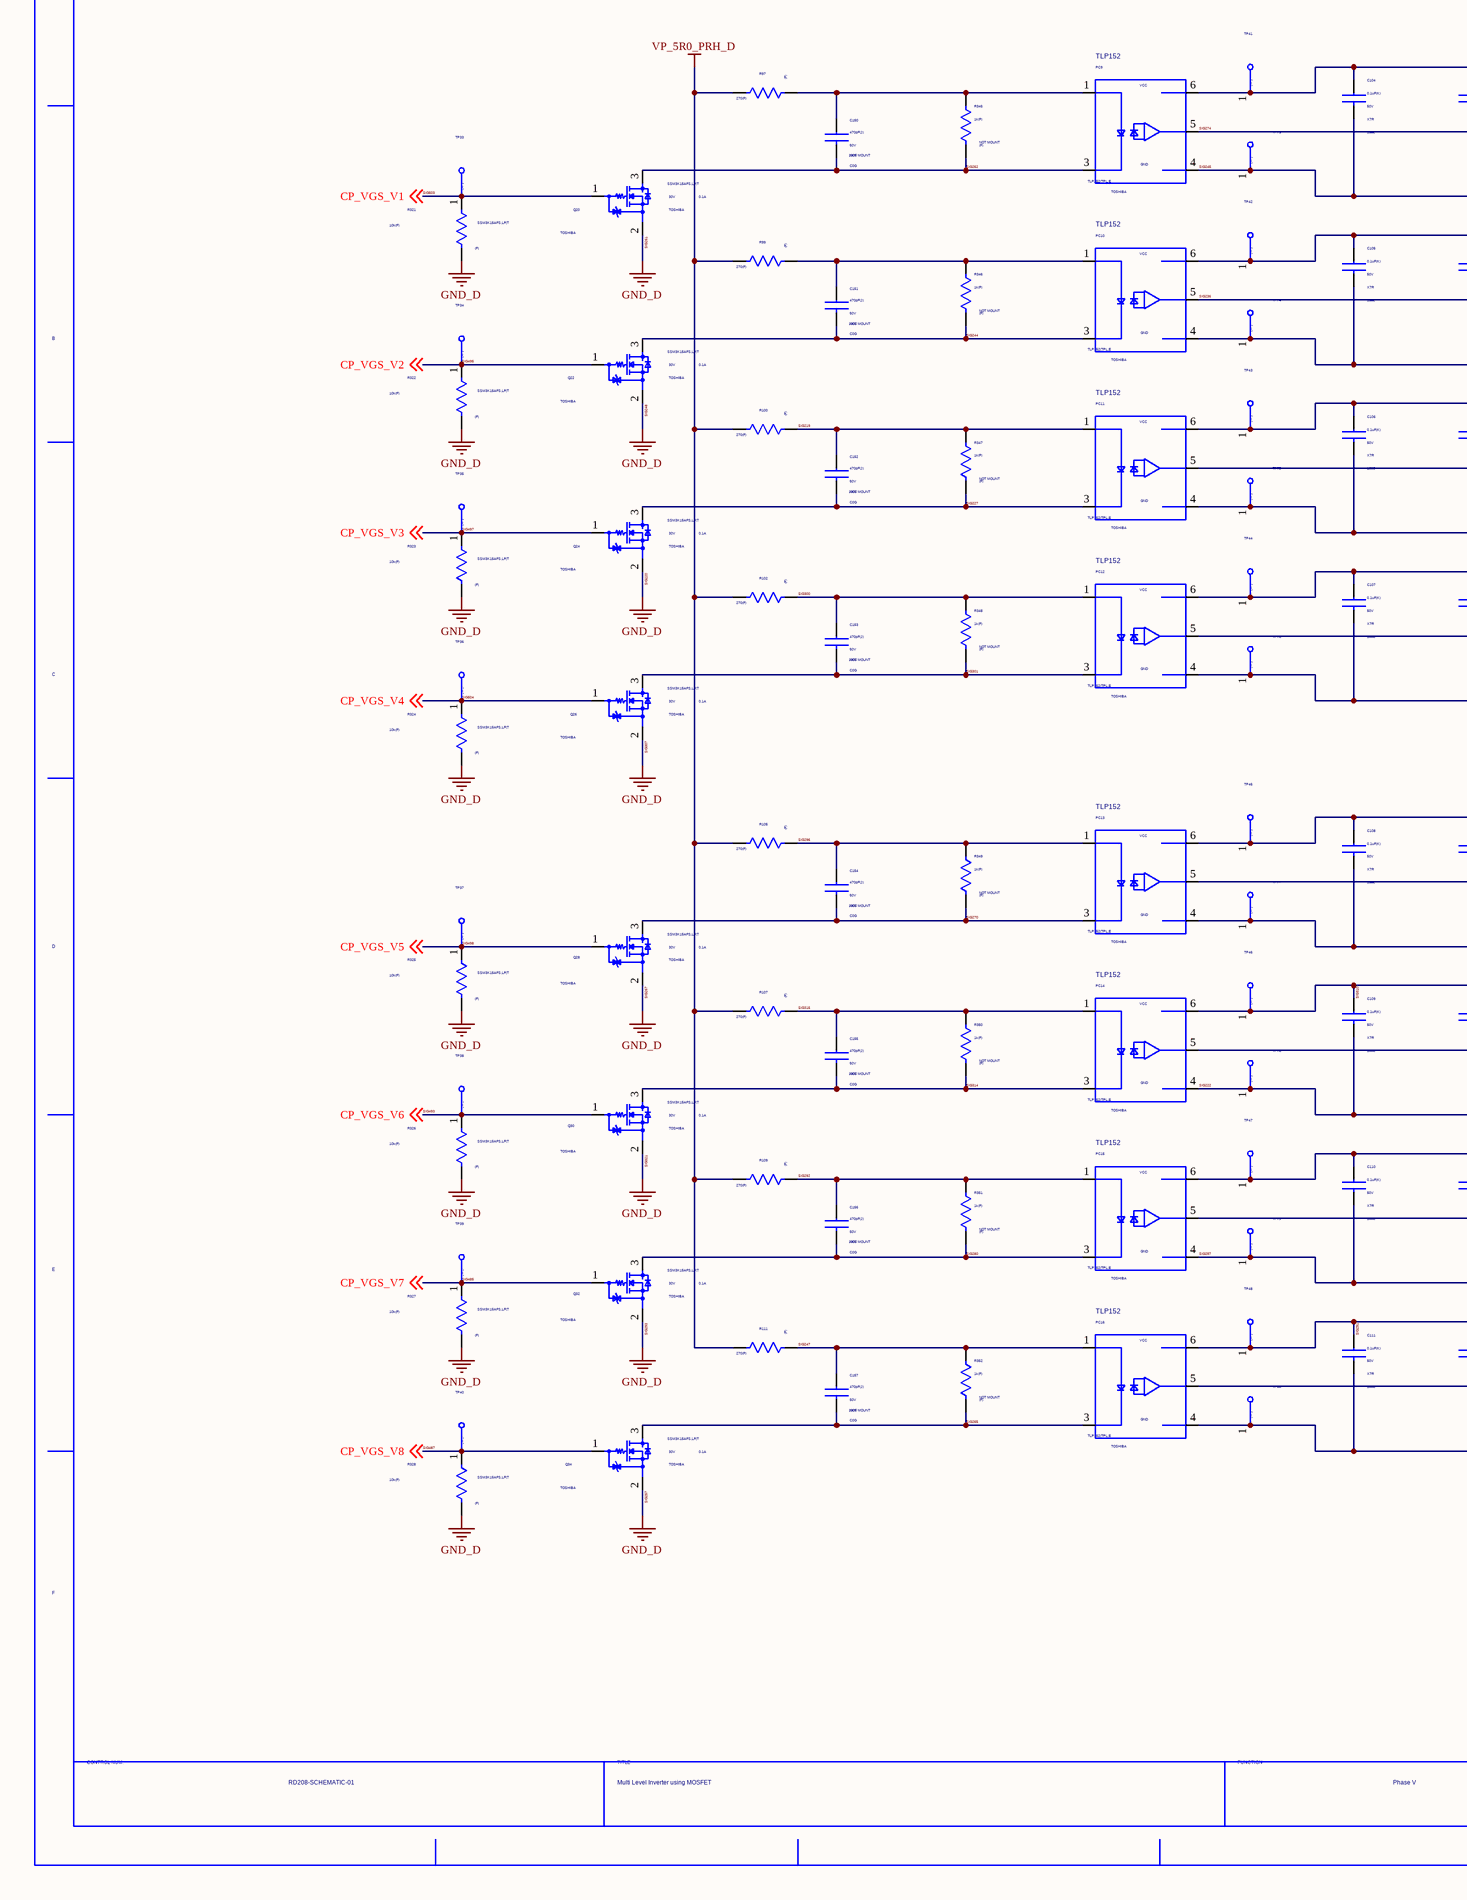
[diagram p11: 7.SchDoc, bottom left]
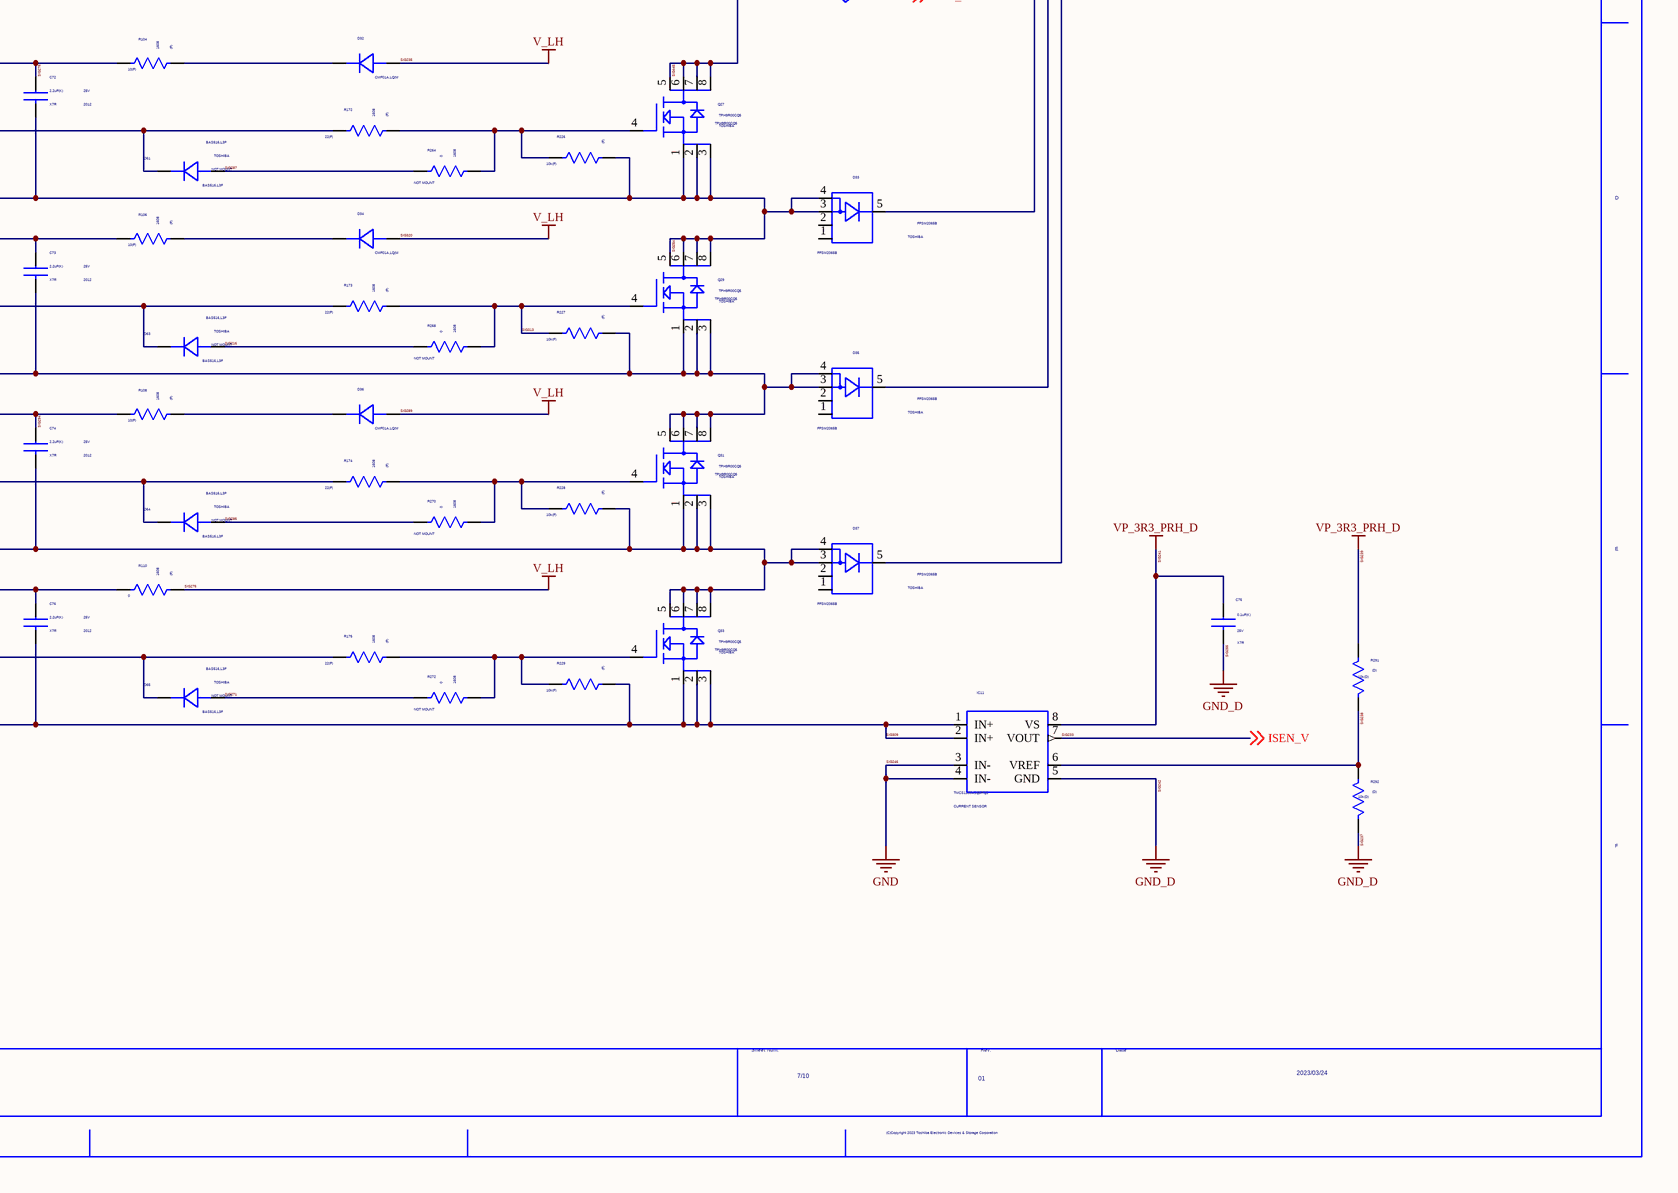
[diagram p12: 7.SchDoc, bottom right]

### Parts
(Parts that share a designator on the sheet are numbered #1, #2 ... from top to bottom, then left to right.)
C62  VAL2: 25V  SIZECODESMD: 2012  VALUE4: X7R  VAL1: 2.2uF(K)  (hidden comment: GRM21BR71E225KE11L)
C63  VAL2: 250V  VAL1: 100uF(M)  (hidden comment: EKMQ251ELL101ML25S)
C64  VAL2: 25V  SIZECODESMD: 2012  VALUE4: X7R  VAL1: 2.2uF(K)  (hidden comment: GRM21BR71E225KE11L)
C65  VAL2: 250V  VAL1: 100uF(M)  (hidden comment: EKMQ251ELL101ML25S)
C68  VAL2: 25V  SIZECODESMD: 2012  VALUE4: X7R  VAL1: 2.2uF(K)  (hidden comment: GRM21BR71E225KE11L)
C69  VAL2: 250V  VAL1: 100uF(M)  (hidden comment: EKMQ251ELL101ML25S)
C70  VAL2: 25V  SIZECODESMD: 2012  VALUE4: X7R  VAL1: 2.2uF(K)  (hidden comment: GRM21BR71E225KE11L)
C71  VAL2: 250V  VAL1: 100uF(M)  (hidden comment: EKMQ251ELL101ML25S)
C72  VAL2: 25V  SIZECODESMD: 2012  VALUE4: X7R  VAL1: 2.2uF(K)  (hidden comment: GRM21BR71E225KE11L)
C73  VAL2: 25V  SIZECODESMD: 2012  VALUE4: X7R  VAL1: 2.2uF(K)  (hidden comment: GRM21BR71E225KE11L)
C74  VAL2: 25V  SIZECODESMD: 2012  VALUE4: X7R  VAL1: 2.2uF(K)  (hidden comment: GRM21BR71E225KE11L)
C75  VAL2: 25V  VALUE4: X7R  VAL1: 0.1uF(K)  (hidden comment: GRM155R71E104KE14D)
C76  VAL2: 25V  SIZECODESMD: 2012  VALUE4: X7R  VAL1: 2.2uF(K)  (hidden comment: GRM21BR71E225KE11L)
C104  VAL2: 50V  SIZECODESMD: 1608  VALUE4: X7R  VAL1: 0.1uF(K)  (hidden comment: C1608X7R1H104K080AA)
C105  VAL2: 50V  SIZECODESMD: 1608  VALUE4: X7R  VAL1: 0.1uF(K)  (hidden comment: C1608X7R1H104K080AA)
C106  VAL2: 50V  SIZECODESMD: 1608  VALUE4: X7R  VAL1: 0.1uF(K)  (hidden comment: C1608X7R1H104K080AA)
C107  VAL2: 50V  SIZECODESMD: 1608  VALUE4: X7R  VAL1: 0.1uF(K)  (hidden comment: C1608X7R1H104K080AA)
C108  VAL2: 50V  SIZECODESMD: 1608  VALUE4: X7R  VAL1: 0.1uF(K)  (hidden comment: C1608X7R1H104K080AA)
C109  VAL2: 50V  SIZECODESMD: 1608  VALUE4: X7R  VAL1: 0.1uF(K)  (hidden comment: C1608X7R1H104K080AA)
C110  VAL2: 50V  SIZECODESMD: 1608  VALUE4: X7R  VAL1: 0.1uF(K)  (hidden comment: C1608X7R1H104K080AA)
C111  VAL2: 50V  SIZECODESMD: 1608  VALUE4: X7R  VAL1: 0.1uF(K)  (hidden comment: C1608X7R1H104K080AA)
C150  VAL2: 50V  SIZECODESMD: 1005  VALUE4: C0G  VAL1: 470pF(J)  NOTMOUNT: NOT MOUNT  (hidden comment: GRM1555C1H471JA01J)
C151  VAL2: 50V  SIZECODESMD: 1005  VALUE4: C0G  VAL1: 470pF(J)  NOTMOUNT: NOT MOUNT  (hidden comment: GRM1555C1H471JA01J)
C152  VAL2: 50V  SIZECODESMD: 1005  VALUE4: C0G  VAL1: 470pF(J)  NOTMOUNT: NOT MOUNT  (hidden comment: GRM1555C1H471JA01J)
C153  VAL2: 50V  SIZECODESMD: 1005  VALUE4: C0G  VAL1: 470pF(J)  NOTMOUNT: NOT MOUNT  (hidden comment: GRM1555C1H471JA01J)
C154  VAL2: 50V  SIZECODESMD: 1005  VALUE4: C0G  VAL1: 470pF(J)  NOTMOUNT: NOT MOUNT  (hidden comment: GRM1555C1H471JA01J)
C155  VAL2: 50V  SIZECODESMD: 1005  VALUE4: C0G  VAL1: 470pF(J)  NOTMOUNT: NOT MOUNT  (hidden comment: GRM1555C1H471JA01J)
C156  VAL2: 50V  SIZECODESMD: 1005  VALUE4: C0G  VAL1: 470pF(J)  NOTMOUNT: NOT MOUNT  (hidden comment: GRM1555C1H471JA01J)
C157  VAL2: 50V  SIZECODESMD: 1005  VALUE4: C0G  VAL1: 470pF(J)  NOTMOUNT: NOT MOUNT  (hidden comment: GRM1555C1H471JA01J)
D26  VAL1: CMF01A,LQ(M  (hidden comment: CMF01A,LQ_M)
D27  USERCOMPTEXT3: TOSHIBA  (hidden comment: FFSM2065B)
D28  VAL1: CMF01A,LQ(M  (hidden comment: CMF01A,LQ_M)
D29  USERCOMPTEXT3: TOSHIBA  (hidden comment: FFSM2065B)
D30  VAL1: CMF01A,LQ(M  (hidden comment: CMF01A,LQ_M)
D31  USERCOMPTEXT3: TOSHIBA  (hidden comment: FFSM2065B)
D32  VAL1: CMF01A,LQ(M  (hidden comment: CMF01A,LQ_M)
D33  USERCOMPTEXT3: TOSHIBA  (hidden comment: FFSM2065B)
D34  VAL1: CMF01A,LQ(M  (hidden comment: CMF01A,LQ_M)
D35  USERCOMPTEXT3: TOSHIBA  (hidden comment: FFSM2065B)
D36  VAL1: CMF01A,LQ(M  (hidden comment: CMF01A,LQ_M)
D37  USERCOMPTEXT3: TOSHIBA  (hidden comment: FFSM2065B)
D58  USERCOMPTEXT3: TOSHIBA  NOTMOUNT: NOT MOUNT  (hidden comment: BAS516,L3F)
D59  USERCOMPTEXT3: TOSHIBA  NOTMOUNT: NOT MOUNT  (hidden comment: BAS516,L3F)
D60  USERCOMPTEXT3: TOSHIBA  NOTMOUNT: NOT MOUNT  (hidden comment: BAS516,L3F)
D61  USERCOMPTEXT3: TOSHIBA  NOTMOUNT: NOT MOUNT  (hidden comment: BAS516,L3F)
D62  USERCOMPTEXT3: TOSHIBA  NOTMOUNT: NOT MOUNT  (hidden comment: BAS516,L3F)
D63  USERCOMPTEXT3: TOSHIBA  NOTMOUNT: NOT MOUNT  (hidden comment: BAS516,L3F)
D64  USERCOMPTEXT3: TOSHIBA  NOTMOUNT: NOT MOUNT  (hidden comment: BAS516,L3F)
D65  USERCOMPTEXT3: TOSHIBA  NOTMOUNT: NOT MOUNT  (hidden comment: BAS516,L3F)
DR2  STAR2  (value not drawn)
IC11  VAL2: CURRENT SENSOR  (hidden comment: TMCS1100A1QDRQ1)
PC9  SCH_NAME: TLP152  USERCOMPTEXT3: TOSHIBA  VAL3: TLP152(TPL,E  (hidden comment: TLP152_TPL,E)
PC10  SCH_NAME: TLP152  USERCOMPTEXT3: TOSHIBA  VAL3: TLP152(TPL,E  (hidden comment: TLP152_TPL,E)
PC11  SCH_NAME: TLP152  USERCOMPTEXT3: TOSHIBA  VAL3: TLP152(TPL,E  (hidden comment: TLP152_TPL,E)
PC12  SCH_NAME: TLP152  USERCOMPTEXT3: TOSHIBA  VAL3: TLP152(TPL,E  (hidden comment: TLP152_TPL,E)
PC13  SCH_NAME: TLP152  USERCOMPTEXT3: TOSHIBA  VAL3: TLP152(TPL,E  (hidden comment: TLP152_TPL,E)
PC14  SCH_NAME: TLP152  USERCOMPTEXT3: TOSHIBA  VAL3: TLP152(TPL,E  (hidden comment: TLP152_TPL,E)
PC15  SCH_NAME: TLP152  USERCOMPTEXT3: TOSHIBA  VAL3: TLP152(TPL,E  (hidden comment: TLP152_TPL,E)
PC16  SCH_NAME: TLP152  USERCOMPTEXT3: TOSHIBA  VAL3: TLP152(TPL,E  (hidden comment: TLP152_TPL,E)
Q19  USERCOMPTEXT3: TOSHIBA  (hidden comment: TPH9R00CQ5)
Q20  VAL2: 0.1A  MANUFACTURER: TOSHIBA  SIZECODESMD: 30V  VAL1: SSM3K15AFS,LF(T  (hidden comment: SSM3K15AFS,LF_T)
Q21  USERCOMPTEXT3: TOSHIBA  (hidden comment: TPH9R00CQ5)
Q22  VAL2: 0.1A  MANUFACTURER: TOSHIBA  SIZECODESMD: 30V  VAL1: SSM3K15AFS,LF(T  (hidden comment: SSM3K15AFS,LF_T)
Q23  USERCOMPTEXT3: TOSHIBA  (hidden comment: TPH9R00CQ5)
Q24  VAL2: 0.1A  MANUFACTURER: TOSHIBA  SIZECODESMD: 30V  VAL1: SSM3K15AFS,LF(T  (hidden comment: SSM3K15AFS,LF_T)
Q25  USERCOMPTEXT3: TOSHIBA  (hidden comment: TPH9R00CQ5)
Q26  VAL2: 0.1A  MANUFACTURER: TOSHIBA  SIZECODESMD: 30V  VAL1: SSM3K15AFS,LF(T  (hidden comment: SSM3K15AFS,LF_T)
Q27  USERCOMPTEXT3: TOSHIBA  (hidden comment: TPH9R00CQ5)
Q28  VAL2: 0.1A  MANUFACTURER: TOSHIBA  SIZECODESMD: 30V  VAL1: SSM3K15AFS,LF(T  (hidden comment: SSM3K15AFS,LF_T)
Q29  USERCOMPTEXT3: TOSHIBA  (hidden comment: TPH9R00CQ5)
Q30  VAL2: 0.1A  MANUFACTURER: TOSHIBA  SIZECODESMD: 30V  VAL1: SSM3K15AFS,LF(T  (hidden comment: SSM3K15AFS,LF_T)
Q31  USERCOMPTEXT3: TOSHIBA  (hidden comment: TPH9R00CQ5)
Q32  VAL2: 0.1A  MANUFACTURER: TOSHIBA  SIZECODESMD: 30V  VAL1: SSM3K15AFS,LF(T  (hidden comment: SSM3K15AFS,LF_T)
Q33  USERCOMPTEXT3: TOSHIBA  (hidden comment: TPH9R00CQ5)
Q34  VAL2: 0.1A  MANUFACTURER: TOSHIBA  SIZECODESMD: 30V  VAL1: SSM3K15AFS,LF(T  (hidden comment: SSM3K15AFS,LF_T)
R96  SIZECODESMD: 1608  VALUE4: (F)  VAL1: 10(F)  (hidden comment: ERJ3EKF10R0V)
R97  VALUE4: (F)  VAL1: 270(F)  (hidden comment: ERJ2RKF2700X)
R98  SIZECODESMD: 1608  VALUE4: (F)  VAL1: 10(F)  (hidden comment: ERJ3EKF10R0V)
R99  VALUE4: (F)  VAL1: 270(F)  (hidden comment: ERJ2RKF2700X)
R100  VALUE4: (F)  VAL1: 270(F)  (hidden comment: ERJ2RKF2700X)
R101  SIZECODESMD: 1608  VALUE4: (F)  VAL1: 10(F)  (hidden comment: ERJ3EKF10R0V)
R102  VALUE4: (F)  VAL1: 270(F)  (hidden comment: ERJ2RKF2700X)
R103  SIZECODESMD: 1608  VALUE4: (F)  VAL1: 0  (hidden comment: ERJ3EKF10R0V)
R104  SIZECODESMD: 1608  VALUE4: (F)  VAL1: 10(F)  (hidden comment: ERJ3EKF10R0V)
R105  VALUE4: (F)  VAL1: 270(F)  (hidden comment: ERJ2RKF2700X)
R106  SIZECODESMD: 1608  VALUE4: (F)  VAL1: 10(F)  (hidden comment: ERJ3EKF10R0V)
R107  VALUE4: (F)  VAL1: 270(F)  (hidden comment: ERJ2RKF2700X)
R108  SIZECODESMD: 1608  VALUE4: (F)  VAL1: 10(F)  (hidden comment: ERJ3EKF10R0V)
R109  VALUE4: (F)  VAL1: 270(F)  (hidden comment: ERJ2RKF2700X)
R110  SIZECODESMD: 1608  VALUE4: (F)  VAL1: 0  (hidden comment: ERJ3EKF10R0V)
R111  VALUE4: (F)  VAL1: 270(F)  (hidden comment: ERJ2RKF2700X)
R168  SIZECODESMD: 1608  VALUE4: (F)  VAL1: 22(F)  (hidden comment: ERJ3EKF22R0V)
R169  SIZECODESMD: 1608  VALUE4: (F)  VAL1: 22(F)  (hidden comment: ERJ3EKF22R0V)
R170  SIZECODESMD: 1608  VALUE4: (F)  VAL1: 22(F)  (hidden comment: ERJ3EKF22R0V)
R171  SIZECODESMD: 1608  VALUE4: (F)  VAL1: 22(F)  (hidden comment: ERJ3EKF22R0V)
R172  SIZECODESMD: 1608  VALUE4: (F)  VAL1: 22(F)  (hidden comment: ERJ3EKF22R0V)
R173  SIZECODESMD: 1608  VALUE4: (F)  VAL1: 22(F)  (hidden comment: ERJ3EKF22R0V)
R174  SIZECODESMD: 1608  VALUE4: (F)  VAL1: 22(F)  (hidden comment: ERJ3EKF22R0V)
R175  SIZECODESMD: 1608  VALUE4: (F)  VAL1: 22(F)  (hidden comment: ERJ3EKF22R0V)
R199  SIZECODESMD: 3216  VALUE4: (D)  VAL1: 470k(D)  (hidden comment: HV73V2BTTD4703D)
R200  SIZECODESMD: 3216  VALUE4: (D)  VAL1: 470k(D)  (hidden comment: HV73V2BTTD4703D)
R201  SIZECODESMD: 3216  VALUE4: (D)  VAL1: 470k(D)  (hidden comment: HV73V2BTTD4703D)
R202  SIZECODESMD: 3216  VALUE4: (D)  VAL1: 470k(D)  (hidden comment: HV73V2BTTD4703D)
R222  VALUE4: (F)  VAL1: 10k(F)  (hidden comment: ERJ2RKF1002X)
R223  VALUE4: (F)  VAL1: 10k(F)  (hidden comment: ERJ2RKF1002X)
R224  VALUE4: (F)  VAL1: 10k(F)  (hidden comment: ERJ2RKF1002X)
R225  VALUE4: (F)  VAL1: 10k(F)  (hidden comment: ERJ2RKF1002X)
R226  VALUE4: (F)  VAL1: 10k(F)  (hidden comment: ERJ2RKF1002X)
R227  VALUE4: (F)  VAL1: 10k(F)  (hidden comment: ERJ2RKF1002X)
R228  VALUE4: (F)  VAL1: 10k(F)  (hidden comment: ERJ2RKF1002X)
R229  VALUE4: (F)  VAL1: 10k(F)  (hidden comment: ERJ2RKF1002X)
R258  SIZECODESMD: 1608  VAL1: 0  NOTMOUNT: NOT MOUNT  (hidden comment: ERJ3GEY0R00V)
R260  SIZECODESMD: 1608  VAL1: 0  NOTMOUNT: NOT MOUNT  (hidden comment: ERJ3GEY0R00V)
R262  SIZECODESMD: 1608  VAL1: 0  NOTMOUNT: NOT MOUNT  (hidden comment: ERJ3GEY0R00V)
R264  SIZECODESMD: 1608  VAL1: 0  NOTMOUNT: NOT MOUNT  (hidden comment: ERJ3GEY0R00V)
R266  SIZECODESMD: 1608  VAL1: 0  NOTMOUNT: NOT MOUNT  (hidden comment: ERJ3GEY0R00V)
R268  SIZECODESMD: 1608  VAL1: 0  NOTMOUNT: NOT MOUNT  (hidden comment: ERJ3GEY0R00V)
R270  SIZECODESMD: 1608  VAL1: 0  NOTMOUNT: NOT MOUNT  (hidden comment: ERJ3GEY0R00V)
R272  SIZECODESMD: 1608  VAL1: 0  NOTMOUNT: NOT MOUNT  (hidden comment: ERJ3GEY0R00V)
R291  VALUE4: (D)  VAL1: 10k(D)  (hidden comment: RK73G1ETTP1002D)
R292  VALUE4: (D)  VAL1: 10k(D)  (hidden comment: RK73G1ETTP1002D)
R321  VALUE4: (F)  VAL1: 10k(F)  (hidden comment: ERJ2RKF1002X)
R322  VALUE4: (F)  VAL1: 10k(F)  (hidden comment: ERJ2RKF1002X)
R323  VALUE4: (F)  VAL1: 10k(F)  (hidden comment: ERJ2RKF1002X)
R324  VALUE4: (F)  VAL1: 10k(F)  (hidden comment: ERJ2RKF1002X)
R325  VALUE4: (F)  VAL1: 10k(F)  (hidden comment: ERJ2RKF1002X)
R326  VALUE4: (F)  VAL1: 10k(F)  (hidden comment: ERJ2RKF1002X)
R327  VALUE4: (F)  VAL1: 10k(F)  (hidden comment: ERJ2RKF1002X)
R328  VALUE4: (F)  VAL1: 10k(F)  (hidden comment: ERJ2RKF1002X)
R345  VALUE4: (F)  VAL1: 1k(F)  NOTMOUNT: NOT MOUNT  (hidden comment: ERJ2RKF1001X)
R346  VALUE4: (F)  VAL1: 1k(F)  NOTMOUNT: NOT MOUNT  (hidden comment: ERJ2RKF1001X)
R347  VALUE4: (F)  VAL1: 1k(F)  NOTMOUNT: NOT MOUNT  (hidden comment: ERJ2RKF1001X)
R348  VALUE4: (F)  VAL1: 1k(F)  NOTMOUNT: NOT MOUNT  (hidden comment: ERJ2RKF1001X)
R349  VALUE4: (F)  VAL1: 1k(F)  NOTMOUNT: NOT MOUNT  (hidden comment: ERJ2RKF1001X)
R350  VALUE4: (F)  VAL1: 1k(F)  NOTMOUNT: NOT MOUNT  (hidden comment: ERJ2RKF1001X)
R351  VALUE4: (F)  VAL1: 1k(F)  NOTMOUNT: NOT MOUNT  (hidden comment: ERJ2RKF1001X)
R352  VALUE4: (F)  VAL1: 1k(F)  NOTMOUNT: NOT MOUNT  (hidden comment: ERJ2RKF1001X)
TP33  TP  (value not drawn)
TP34  TP  (value not drawn)
TP35  TP  (value not drawn)
TP36  TP  (value not drawn)
TP37  TP  (value not drawn)
TP38  TP  (value not drawn)
TP39  TP  (value not drawn)
TP40  TP  (value not drawn)
TP41  TP  (value not drawn)
TP42  TP  (value not drawn)
TP43  TP  (value not drawn)
TP44  TP  (value not drawn)
TP45  TP  (value not drawn)
TP46  TP  (value not drawn)
TP47  TP  (value not drawn)
TP48  TP  (value not drawn)
TP73  TP  (value not drawn)
TP74  TP  (value not drawn)
TP75  TP  (value not drawn)
TP76  TP  (value not drawn)
TP77  TP  (value not drawn)
TP78  TP  (value not drawn)
TP79  TP  (value not drawn)
TP80  TP  (value not drawn)
U?#7  DATE: 2023/03/24  TITLE: Multi Level Inverter using MOSFET  REVISION: 01  SHEETNUMBER: 7/10  DRAWINGNUMBER: RD208-SCHEMATIC-01  FUNCTION: Phase V  (hidden comment: WAKU_DEF_A3)

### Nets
GND: C71.2 IC11.3(IN-) IC11.4(IN-) R202.2  [also labelled SIG246, SIG264, SIG279]  [project net SIG200]
GND_D: C75.2 IC11.5(GND) Q20.2(E) Q22.2(E) Q24.2(E) Q26.2(E) Q28.2(E) Q30.2(E) Q32.2(E) Q34.2(E) R292.1 R321.2 R322.2 R323.2 R324.2 R325.2 R326.2 R327.2 R328.2  [also labelled SIG220, SIG237, SIG242, SIG248, SIG255, SIG257, SIG261, SIG267, SIG293, SIG307, SIG321]  [project net SIG10]
SIG235: D32.A(ANODE) D34.A(ANODE) D36.A(ANODE) R110.2  [also labelled SIG275, SIG289, SIG320, V_LH]
SIG239: C75.1 IC11.8(VS) R291.2  [also labelled SIG241, VP_3R3_PRH_D]  [project net SIG107]
SIG318: C63.1 Q19.5(D1) Q19.6(D2) Q19.7(D3) Q19.8(D4) R199.1  [also labelled VP_380R0_INV]  [project net SIG1]
SIG445: C70.2 C107.2 DR2.1 PC12.4 Q25.1(S1) Q25.2(S2) Q25.3(S3) Q27.5(D1) Q27.6(D2) Q27.7(D3) Q27.8(D4) R225.2 TP76.1  [also labelled V_VL]
V_VH: D26.A(ANODE) D28.A(ANODE) D30.A(ANODE) R103.2
VP_5R0_PRH_D: R97.1 R99.1 R100.1 R102.1 R105.1 R107.1 R109.1 R111.1  [project net SIG104]
OUT_V: DR2.2 ; off-sheet OUT_V
SIG209: D60.K(CATHODE) PC11.5 R170.1
SIG210: C68.2 C106.2 D31.5(CATHODE) PC11.4 Q23.1(S1) Q23.2(S2) Q23.3(S3) Q25.5(D1) Q25.6(D2) Q25.7(D3) Q25.8(D4) R224.2 TP75.1
SIG214: D60.A(ANODE) R262.1
SIG215: D32.K(CATHODE) R104.2
SIG216: D63.A(ANODE) R268.1
SIG219: C152.1 PC11.1 R100.2 R347.1
SIG221: C63.2 C65.1 D27.3(ANODE3) D27.4(ANODE4) D33.5(CATHODE) R199.2 R200.1
SIG222: C73.2 C109.2 D35.3(ANODE3) D35.4(ANODE4) PC14.4 Q29.1(S1) Q29.2(S2) Q29.3(S3) Q31.5(D1) Q31.6(D2) Q31.7(D3) Q31.8(D4) R227.2 TP78.1
SIG223: C68.1 C106.1 PC11.6 R101.1 TP43.1
SIG225: D61.K(CATHODE) PC13.5 R172.1
SIG226: C65.2 C69.1 D29.3(ANODE3) D29.4(ANODE4) D35.5(CATHODE) R200.2 R201.1
SIG227: C152.2 PC11.3 Q24.3(C) R347.2
SIG230: D28.K(CATHODE) R98.2
SIG231: D64.K(CATHODE) PC15.5 R174.1
SIG232: D34.K(CATHODE) R106.2
SIG233: IC11.7(VOUT) ; off-sheet ISEN_V  [also labelled ISEN_V]
SIG236: D59.K(CATHODE) PC10.5 R169.1
SIG238: IC11.6(VREF) R291.1 R292.2
SIG243: Q21.4(G) R169.2 R223.1 R260.2
SIG244: C151.2 PC10.3 Q22.3(C) R346.2
SIG245: C62.2 C104.2 D27.5(CATHODE) PC9.4 Q19.1(S1) Q19.2(S2) Q19.3(S3) Q21.5(D1) Q21.6(D2) Q21.7(D3) Q21.8(D4) R222.2 TP73.1
SIG247: C157.1 PC16.1 R111.2 R352.1
SIG252: D36.K(CATHODE) R108.2
SIG253: C69.2 C71.1 D31.3(ANODE3) D31.4(ANODE4) D37.5(CATHODE) R201.2 R202.1
SIG254: C72.2 C108.2 D33.3(ANODE3) D33.4(ANODE4) PC13.4 Q27.1(S1) Q27.2(S2) Q27.3(S3) Q29.5(D1) Q29.6(D2) Q29.7(D3) Q29.8(D4) R226.2 TP77.1
SIG256: Q27.4(G) R172.2 R226.1 R264.2
SIG258: C64.1 C105.1 PC10.6 R98.1 TP42.1
SIG260: D58.A(ANODE) R258.1
SIG262: C150.2 PC9.3 Q20.3(C) R345.2
SIG263: Q33.4(G) R175.2 R229.1 R272.2
SIG265: C157.2 PC16.3 Q34.3(C) R352.2
SIG266: D59.A(ANODE) R260.1
SIG269: C151.1 PC10.1 R99.2 R346.1
SIG270: C154.2 PC13.3 Q28.3(C) R349.2
SIG271: D65.A(ANODE) R272.1
SIG272: D65.K(CATHODE) PC16.5 R175.1
SIG274: D58.K(CATHODE) PC9.5 R168.1
SIG276: C150.1 PC9.1 R97.2 R345.1
SIG278: C72.1 C108.1 PC13.6 R104.1 TP45.1
SIG280: C156.2 PC15.3 Q32.3(C) R351.2
SIG281: C62.1 C104.1 PC9.6 R96.1 TP41.1
SIG282: Q19.4(G) R168.2 R222.1 R258.2
SIG285: D26.K(CATHODE) R96.2
SIG286: D64.A(ANODE) R270.1
SIG287: D61.A(ANODE) R264.1
SIG291: C76.1 C111.1 PC16.6 R110.1 TP48.1
SIG292: C156.1 PC15.1 R109.2 R351.1
SIG294: C74.1 C110.1 PC15.6 R108.1 TP47.1
SIG295: Q31.4(G) R174.2 R228.1 R270.2
SIG296: C154.1 PC13.1 R105.2 R349.1
SIG297: C74.2 C110.2 D37.3(ANODE3) D37.4(ANODE4) PC15.4 Q31.1(S1) Q31.2(S2) Q31.3(S3) Q33.5(D1) Q33.6(D2) Q33.7(D3) Q33.8(D4) R228.2 TP79.1
SIG298: D30.K(CATHODE) R101.2
SIG299: C64.2 C105.2 D29.5(CATHODE) PC10.4 Q21.1(S1) Q21.2(S2) Q21.3(S3) Q23.5(D1) Q23.6(D2) Q23.7(D3) Q23.8(D4) R223.2 TP74.1
SIG300: C153.1 PC12.1 R102.2 R348.1
SIG301: C153.2 PC12.3 Q26.3(C) R348.2
SIG302: C70.1 C107.1 PC12.6 R103.1 TP44.1
SIG305: Q25.4(G) R171.2 R225.1 R266.2
SIG306: D62.A(ANODE) R266.1
SIG309: C76.2 C111.2 IC11.1(IN+) IC11.2(IN+) PC16.4 Q33.1(S1) Q33.2(S2) Q33.3(S3) R229.2 TP80.1
SIG310: C73.1 C109.1 PC14.6 R106.1 TP46.1
SIG313: Q29.4(G) R173.2 R227.1 R268.2
SIG314: C155.2 PC14.3 Q30.3(C) R350.2
SIG315: C155.1 PC14.1 R107.2 R350.1
SIG316: D62.K(CATHODE) PC12.5 R171.1
SIG317: Q23.4(G) R170.2 R224.1 R262.2
SIG319: D63.K(CATHODE) PC14.5 R173.1
SIG485: Q32.1(B) R327.1 TP39.1 ; off-sheet CP_VGS_V7  [also labelled CP_VGS_V7]
SIG487: Q34.1(B) R328.1 TP40.1 ; off-sheet CP_VGS_V8  [also labelled CP_VGS_V8]
SIG493: Q30.1(B) R326.1 TP38.1 ; off-sheet CP_VGS_V6  [also labelled CP_VGS_V6]
SIG495: Q22.1(B) R322.1 TP34.1 ; off-sheet CP_VGS_V2  [also labelled CP_VGS_V2]
SIG497: Q24.1(B) R323.1 TP35.1 ; off-sheet CP_VGS_V3  [also labelled CP_VGS_V3]
SIG498: Q28.1(B) R325.1 TP37.1 ; off-sheet CP_VGS_V5  [also labelled CP_VGS_V5]
SIG503: Q20.1(B) R321.1 TP33.1 ; off-sheet CP_VGS_V1  [also labelled CP_VGS_V1]
SIG504: Q26.1(B) R324.1 TP36.1 ; off-sheet CP_VGS_V4  [also labelled CP_VGS_V4]

Not connected (* = marked no-connect by the designer): D27 1(NC1) 2(NC2); D29 1(NC1) 2(NC2); D31 1(NC1) 2(NC2); D33 1(NC1) 2(NC2); D35 1(NC1) 2(NC2); D37 1(NC1) 2(NC2)

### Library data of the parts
C62 C64 C68 C70 C72-C74 C76 = GRM21BR71E225KE11L: as C47 on sheet 6
C63 = EKMQ251ELL101ML25S: as C48 on sheet 6
C65 = EKMQ251ELL101ML25S: as C49 on sheet 6
C69 = EKMQ251ELL101ML25S: as C54 on sheet 6
C71 = EKMQ251ELL101ML25S: as C56 on sheet 6
C75 = GRM155R71E104KE14D: as C61 on sheet 6
C104-C111 = C1608X7R1H104K080AA: as C112 on sheet 6
C150-C157 = GRM1555C1H471JA01J: as C142 on sheet 6
D26 D28 D30 D32 D34 D36 = CMF01A,LQ_M: as D14 on sheet 6
D27 D29 D31 D33 D35 D37 = FFSM2065B: as D15 on sheet 6
D58-D65 = BAS516,L3F: as D50 on sheet 6
DR2 = STAR2: as DR1 on sheet 6
IC11 = TMCS1100A1QDRQ1: as IC10 on sheet 6
PC9-PC16 = TLP152_TPL,E: as PC1 on sheet 6
Q19 Q21 Q23 Q25 Q27 Q29 Q31 Q33 = TPH9R00CQ5: as Q3 on sheet 6
Q20 Q22 Q24 Q26 Q28 Q30 Q32 Q34 = SSM3K15AFS,LF_T: as Q4 on sheet 6
R96 R98 R101 R104 R106 R108 = ERJ3EKF10R0V: as R80 on sheet 6
R97 R99 R100 R102 R105 R107 R109 R111 = ERJ2RKF2700X: as R81 on sheet 6
R103 R110 = ERJ3EKF10R0V: as R86 on sheet 6
R168-R175 = ERJ3EKF22R0V: as R176 on sheet 6
R199 = HV73V2BTTD4703D: as R193 on sheet 6
R200 = HV73V2BTTD4703D: as R194 on sheet 6
R201 = HV73V2BTTD4703D: as R195 on sheet 6
R202 = HV73V2BTTD4703D: as R196 on sheet 6
R222-R229 = ERJ2RKF1002X: as R214 on sheet 6
R258 R260 R262 R264 R266 R268 R270 R272 = ERJ3GEY0R00V: as R245 on sheet 6
R291 = RK73G1ETTP1002D: as R289 on sheet 6
R292 = RK73G1ETTP1002D: as R290 on sheet 6
R321-R328 = ERJ2RKF1002X: as R313 on sheet 6
R345-R352 = ERJ2RKF1001X: as R337 on sheet 6
TP33-TP48 TP73-TP80 = TP: as TP17-TP32 on sheet 6
U?#7 = WAKU_DEF_A3: PLOTTIME: HH:MM; SAVEAREA0: -311037,-554865,914355,115662; TIME: 14:30:25; UPDATEUSER: PS4_common_PC; UPDATETIME: 08:25:30; SAVECOUNT: 18; ZONEOFFSETX: 36; ZONEOFFSETY: -24; OriginalSymbolOrigin: (12700,-12700)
